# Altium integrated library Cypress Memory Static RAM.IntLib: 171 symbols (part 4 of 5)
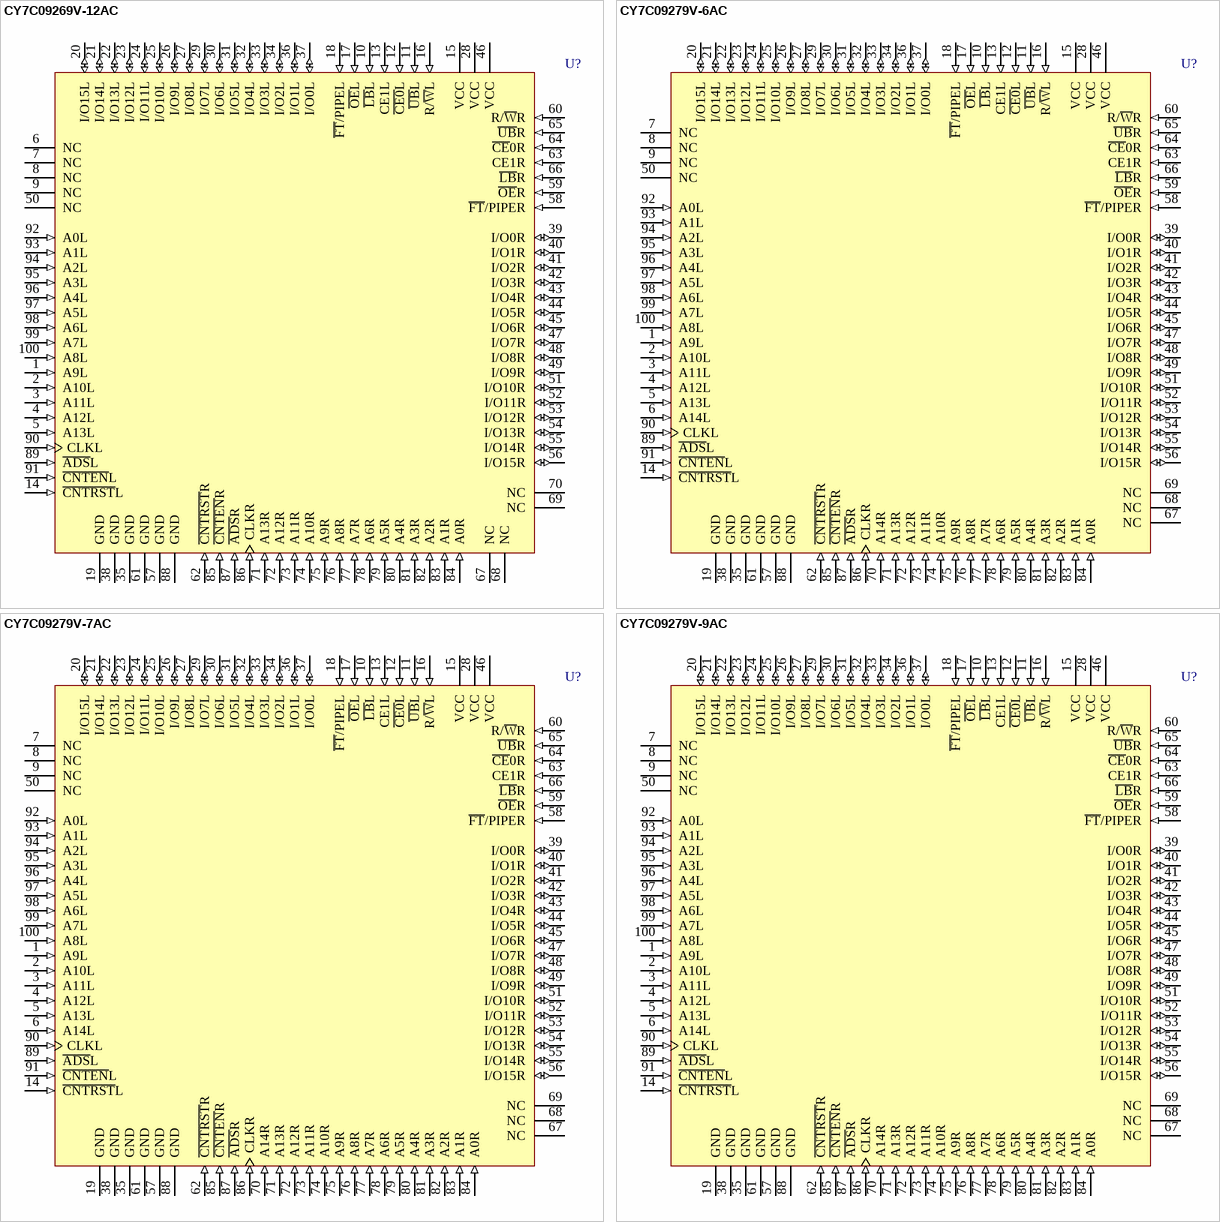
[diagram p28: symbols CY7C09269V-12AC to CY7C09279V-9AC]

## CY7C09279V-7AC
designator U?
3.3V 32K x 16 Synchronous Dual-Port Static RAM
footprint A100_N (Thin QFP, 100-Leads, Body 14x14mm, Pitch 0.5mm, IPC Medium Density)
footprint A100_L (Thin QFP, 100-Leads, Body 14x14mm, Pitch 0.5mm, IPC High Density)
footprint A100_M (Thin QFP, 100-Leads, Body 14x14mm, Pitch 0.5mm, IPC Low Density)
3D model CY7C09279V-A100 (100-Pin Thin Quad Flat Pack 0.5 mm Pitch)
pins: 1 A9L (in), 2 A10L (in), 3 A11L (in), 4 A12L (in), 5 A13L (in), 6 A14L (in), 7 NC, 8 NC, 9 NC, 10 ~{LB}L (in), 11 ~{UB}L (in), 12 ~{CE0}L (in), 13 CE1L (in), 14 ~{CNTRST}L (in), 15 VCC (power), 16 R/~{W}L (in), 17 ~{OE}L (in), 18 ~{FT}/PIPEL (in), 19 GND (power), 20 I/O15L (io), 21 I/O14L (io), 22 I/O13L (io), 23 I/O12L (io), 24 I/O11L (io), 25 I/O10L (io), 26 I/O9L (io), 27 I/O8L (io), 28 VCC (power), 29 I/O7L (io), 30 I/O6L (io), 31 I/O5L (io), 32 I/O4L (io), 33 I/O3L (io), 34 I/O2L (io), 35 GND (power), 36 I/O1L (io), 37 I/O0L (io), 38 GND (power), 39 I/O0R (io), 40 I/O1R (io), 41 I/O2R (io), 42 I/O3R (io), 43 I/O4R (io), 44 I/O5R (io), 45 I/O6R (io), 46 VCC (power), 47 I/O7R (io), 48 I/O8R (io), 49 I/O9R (io), 50 NC, 51 I/O10R (io), 52 I/O11R (io), 53 I/O12R (io), 54 I/O13R (io), 55 I/O14R (io), 56 I/O15R (io), 57 GND (power), 58 ~{FT}/PIPER (in), 59 ~{OE}R (in), 60 R/~{W}R (in), 61 GND (power), 62 ~{CNTRST}R (in), 63 CE1R (in), 64 ~{CE}0R (in), 65 ~{UB}R (in), 66 ~{LB}R (in), 67 NC, 68 NC, 69 NC, 70 A14R (in), 71 A13R (in), 72 A12R (in), 73 A11R (in), 74 A10R (in), 75 A9R (in), 76 A8R (in), 77 A7R (in), 78 A6R (in), 79 A5R (in), 80 A4R (in), 81 A3R (in), 82 A2R (in), 83 A1R (in), 84 A0R (in), 85 ~{CNTEN}R (in), 86 CLKR (in), 87 ~{ADS}R (in), 88 GND (power), 89 ~{ADS}L (in), 90 CLKL (in), 91 ~{CNTEN}L (in), 92 A0L (in), 93 A1L (in), 94 A2L (in), 95 A3L (in), 96 A4L (in), 97 A5L (in), 98 A6L (in), 99 A7L (in), 100 A8L (in)

## CY7C09279V-9AC
designator U?
3.3V 32K x 16 Synchronous Dual-Port Static RAM
footprint A100_N (Thin QFP, 100-Leads, Body 14x14mm, Pitch 0.5mm, IPC Medium Density)
footprint A100_L (Thin QFP, 100-Leads, Body 14x14mm, Pitch 0.5mm, IPC High Density)
footprint A100_M (Thin QFP, 100-Leads, Body 14x14mm, Pitch 0.5mm, IPC Low Density)
3D model CY7C09279V-A100 (100-Pin Thin Quad Flat Pack 0.5 mm Pitch)
pins: 1 A9L (in), 2 A10L (in), 3 A11L (in), 4 A12L (in), 5 A13L (in), 6 A14L (in), 7 NC, 8 NC, 9 NC, 10 ~{LB}L (in), 11 ~{UB}L (in), 12 ~{CE0}L (in), 13 CE1L (in), 14 ~{CNTRST}L (in), 15 VCC (power), 16 R/~{W}L (in), 17 ~{OE}L (in), 18 ~{FT}/PIPEL (in), 19 GND (power), 20 I/O15L (io), 21 I/O14L (io), 22 I/O13L (io), 23 I/O12L (io), 24 I/O11L (io), 25 I/O10L (io), 26 I/O9L (io), 27 I/O8L (io), 28 VCC (power), 29 I/O7L (io), 30 I/O6L (io), 31 I/O5L (io), 32 I/O4L (io), 33 I/O3L (io), 34 I/O2L (io), 35 GND (power), 36 I/O1L (io), 37 I/O0L (io), 38 GND (power), 39 I/O0R (io), 40 I/O1R (io), 41 I/O2R (io), 42 I/O3R (io), 43 I/O4R (io), 44 I/O5R (io), 45 I/O6R (io), 46 VCC (power), 47 I/O7R (io), 48 I/O8R (io), 49 I/O9R (io), 50 NC, 51 I/O10R (io), 52 I/O11R (io), 53 I/O12R (io), 54 I/O13R (io), 55 I/O14R (io), 56 I/O15R (io), 57 GND (power), 58 ~{FT}/PIPER (in), 59 ~{OE}R (in), 60 R/~{W}R (in), 61 GND (power), 62 ~{CNTRST}R (in), 63 CE1R (in), 64 ~{CE}0R (in), 65 ~{UB}R (in), 66 ~{LB}R (in), 67 NC, 68 NC, 69 NC, 70 A14R (in), 71 A13R (in), 72 A12R (in), 73 A11R (in), 74 A10R (in), 75 A9R (in), 76 A8R (in), 77 A7R (in), 78 A6R (in), 79 A5R (in), 80 A4R (in), 81 A3R (in), 82 A2R (in), 83 A1R (in), 84 A0R (in), 85 ~{CNTEN}R (in), 86 CLKR (in), 87 ~{ADS}R (in), 88 GND (power), 89 ~{ADS}L (in), 90 CLKL (in), 91 ~{CNTEN}L (in), 92 A0L (in), 93 A1L (in), 94 A2L (in), 95 A3L (in), 96 A4L (in), 97 A5L (in), 98 A6L (in), 99 A7L (in), 100 A8L (in)

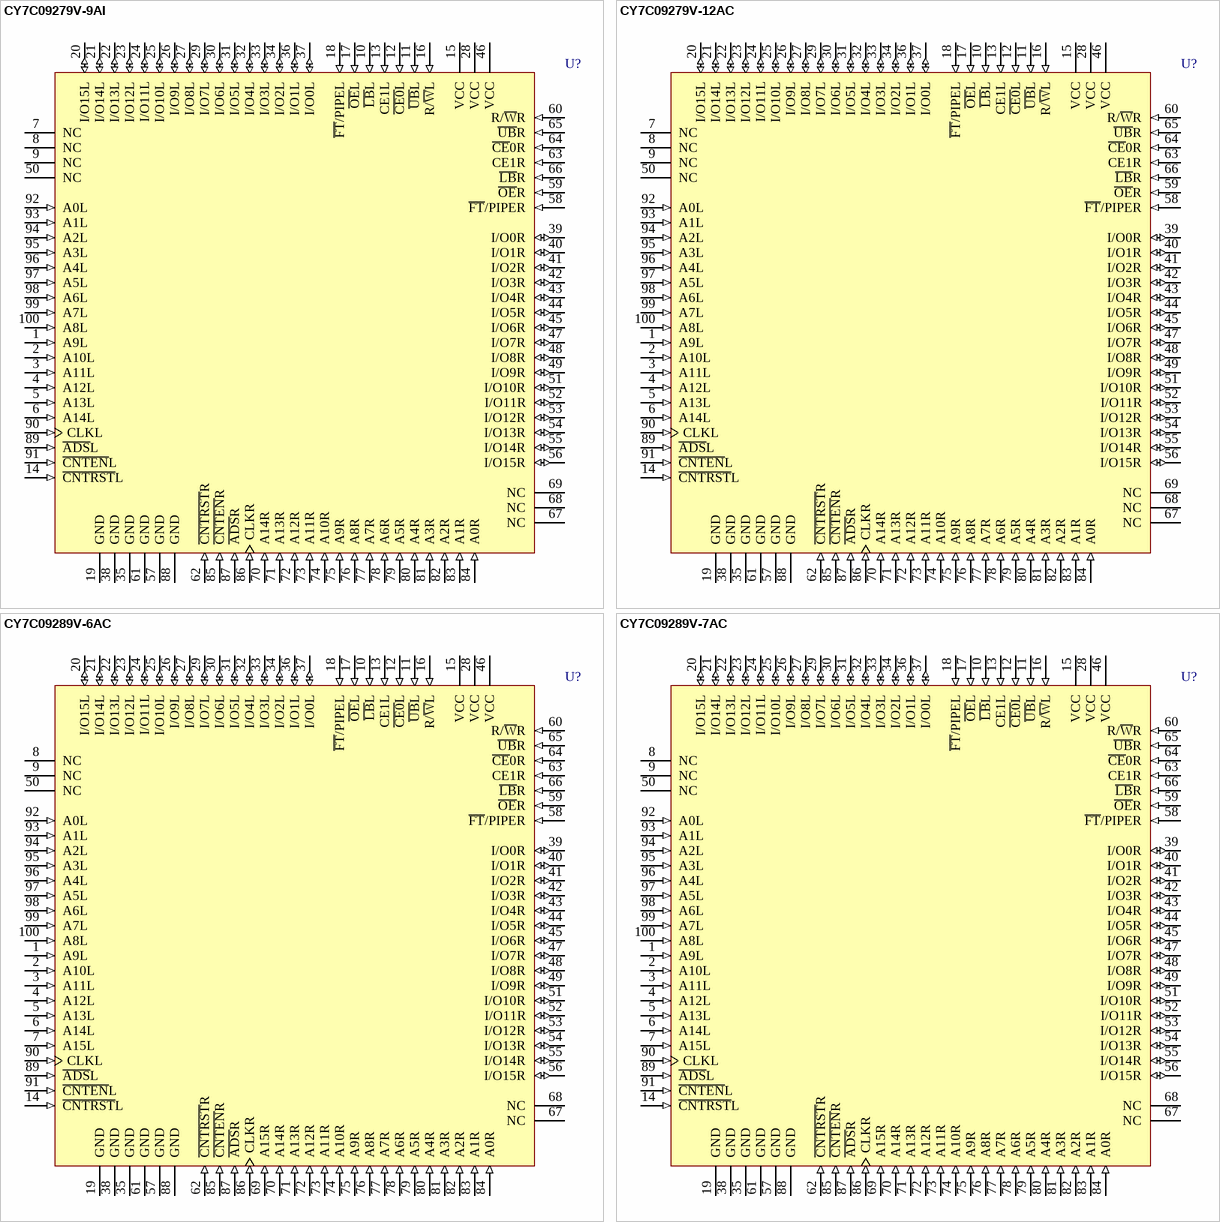
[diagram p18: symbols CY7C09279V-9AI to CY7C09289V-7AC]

## CY7C09279V-9AI
designator U?
3.3V 32K x 16 Synchronous Dual-Port Static RAM
footprint A100_N (Thin QFP, 100-Leads, Body 14x14mm, Pitch 0.5mm, IPC Medium Density)
footprint A100_L (Thin QFP, 100-Leads, Body 14x14mm, Pitch 0.5mm, IPC High Density)
footprint A100_M (Thin QFP, 100-Leads, Body 14x14mm, Pitch 0.5mm, IPC Low Density)
3D model CY7C09279V-A100 (100-Pin Thin Quad Flat Pack 0.5 mm Pitch)
pins: 1 A9L (in), 2 A10L (in), 3 A11L (in), 4 A12L (in), 5 A13L (in), 6 A14L (in), 7 NC, 8 NC, 9 NC, 10 ~{LB}L (in), 11 ~{UB}L (in), 12 ~{CE0}L (in), 13 CE1L (in), 14 ~{CNTRST}L (in), 15 VCC (power), 16 R/~{W}L (in), 17 ~{OE}L (in), 18 ~{FT}/PIPEL (in), 19 GND (power), 20 I/O15L (io), 21 I/O14L (io), 22 I/O13L (io), 23 I/O12L (io), 24 I/O11L (io), 25 I/O10L (io), 26 I/O9L (io), 27 I/O8L (io), 28 VCC (power), 29 I/O7L (io), 30 I/O6L (io), 31 I/O5L (io), 32 I/O4L (io), 33 I/O3L (io), 34 I/O2L (io), 35 GND (power), 36 I/O1L (io), 37 I/O0L (io), 38 GND (power), 39 I/O0R (io), 40 I/O1R (io), 41 I/O2R (io), 42 I/O3R (io), 43 I/O4R (io), 44 I/O5R (io), 45 I/O6R (io), 46 VCC (power), 47 I/O7R (io), 48 I/O8R (io), 49 I/O9R (io), 50 NC, 51 I/O10R (io), 52 I/O11R (io), 53 I/O12R (io), 54 I/O13R (io), 55 I/O14R (io), 56 I/O15R (io), 57 GND (power), 58 ~{FT}/PIPER (in), 59 ~{OE}R (in), 60 R/~{W}R (in), 61 GND (power), 62 ~{CNTRST}R (in), 63 CE1R (in), 64 ~{CE}0R (in), 65 ~{UB}R (in), 66 ~{LB}R (in), 67 NC, 68 NC, 69 NC, 70 A14R (in), 71 A13R (in), 72 A12R (in), 73 A11R (in), 74 A10R (in), 75 A9R (in), 76 A8R (in), 77 A7R (in), 78 A6R (in), 79 A5R (in), 80 A4R (in), 81 A3R (in), 82 A2R (in), 83 A1R (in), 84 A0R (in), 85 ~{CNTEN}R (in), 86 CLKR (in), 87 ~{ADS}R (in), 88 GND (power), 89 ~{ADS}L (in), 90 CLKL (in), 91 ~{CNTEN}L (in), 92 A0L (in), 93 A1L (in), 94 A2L (in), 95 A3L (in), 96 A4L (in), 97 A5L (in), 98 A6L (in), 99 A7L (in), 100 A8L (in)

## CY7C09279V-12AC
designator U?
3.3V 32K x 16 Synchronous Dual-Port Static RAM
footprint A100_N (Thin QFP, 100-Leads, Body 14x14mm, Pitch 0.5mm, IPC Medium Density)
footprint A100_L (Thin QFP, 100-Leads, Body 14x14mm, Pitch 0.5mm, IPC High Density)
footprint A100_M (Thin QFP, 100-Leads, Body 14x14mm, Pitch 0.5mm, IPC Low Density)
3D model CY7C09279V-A100 (100-Pin Thin Quad Flat Pack 0.5 mm Pitch)
pins: 1 A9L (in), 2 A10L (in), 3 A11L (in), 4 A12L (in), 5 A13L (in), 6 A14L (in), 7 NC, 8 NC, 9 NC, 10 ~{LB}L (in), 11 ~{UB}L (in), 12 ~{CE0}L (in), 13 CE1L (in), 14 ~{CNTRST}L (in), 15 VCC (power), 16 R/~{W}L (in), 17 ~{OE}L (in), 18 ~{FT}/PIPEL (in), 19 GND (power), 20 I/O15L (io), 21 I/O14L (io), 22 I/O13L (io), 23 I/O12L (io), 24 I/O11L (io), 25 I/O10L (io), 26 I/O9L (io), 27 I/O8L (io), 28 VCC (power), 29 I/O7L (io), 30 I/O6L (io), 31 I/O5L (io), 32 I/O4L (io), 33 I/O3L (io), 34 I/O2L (io), 35 GND (power), 36 I/O1L (io), 37 I/O0L (io), 38 GND (power), 39 I/O0R (io), 40 I/O1R (io), 41 I/O2R (io), 42 I/O3R (io), 43 I/O4R (io), 44 I/O5R (io), 45 I/O6R (io), 46 VCC (power), 47 I/O7R (io), 48 I/O8R (io), 49 I/O9R (io), 50 NC, 51 I/O10R (io), 52 I/O11R (io), 53 I/O12R (io), 54 I/O13R (io), 55 I/O14R (io), 56 I/O15R (io), 57 GND (power), 58 ~{FT}/PIPER (in), 59 ~{OE}R (in), 60 R/~{W}R (in), 61 GND (power), 62 ~{CNTRST}R (in), 63 CE1R (in), 64 ~{CE}0R (in), 65 ~{UB}R (in), 66 ~{LB}R (in), 67 NC, 68 NC, 69 NC, 70 A14R (in), 71 A13R (in), 72 A12R (in), 73 A11R (in), 74 A10R (in), 75 A9R (in), 76 A8R (in), 77 A7R (in), 78 A6R (in), 79 A5R (in), 80 A4R (in), 81 A3R (in), 82 A2R (in), 83 A1R (in), 84 A0R (in), 85 ~{CNTEN}R (in), 86 CLKR (in), 87 ~{ADS}R (in), 88 GND (power), 89 ~{ADS}L (in), 90 CLKL (in), 91 ~{CNTEN}L (in), 92 A0L (in), 93 A1L (in), 94 A2L (in), 95 A3L (in), 96 A4L (in), 97 A5L (in), 98 A6L (in), 99 A7L (in), 100 A8L (in)

## CY7C09289V-6AC
designator U?
3.3V 64K x 16 Synchronous Dual-Port Static RAM
footprint A100_N (Thin QFP, 100-Leads, Body 14x14mm, Pitch 0.5mm, IPC Medium Density)
footprint A100_L (Thin QFP, 100-Leads, Body 14x14mm, Pitch 0.5mm, IPC High Density)
footprint A100_M (Thin QFP, 100-Leads, Body 14x14mm, Pitch 0.5mm, IPC Low Density)
3D model CY7C09289V-A100 (100-Pin Thin Quad Flat Pack 0.5 mm Pitch)
pins: 1 A9L (in), 2 A10L (in), 3 A11L (in), 4 A12L (in), 5 A13L (in), 6 A14L (in), 7 A15L (in), 8 NC, 9 NC, 10 ~{LB}L (in), 11 ~{UB}L (in), 12 ~{CE0}L (in), 13 CE1L (in), 14 ~{CNTRST}L (in), 15 VCC (power), 16 R/~{W}L (in), 17 ~{OE}L (in), 18 ~{FT}/PIPEL (in), 19 GND (power), 20 I/O15L (io), 21 I/O14L (io), 22 I/O13L (io), 23 I/O12L (io), 24 I/O11L (io), 25 I/O10L (io), 26 I/O9L (io), 27 I/O8L (io), 28 VCC (power), 29 I/O7L (io), 30 I/O6L (io), 31 I/O5L (io), 32 I/O4L (io), 33 I/O3L (io), 34 I/O2L (io), 35 GND (power), 36 I/O1L (io), 37 I/O0L (io), 38 GND (power), 39 I/O0R (io), 40 I/O1R (io), 41 I/O2R (io), 42 I/O3R (io), 43 I/O4R (io), 44 I/O5R (io), 45 I/O6R (io), 46 VCC (power), 47 I/O7R (io), 48 I/O8R (io), 49 I/O9R (io), 50 NC, 51 I/O10R (io), 52 I/O11R (io), 53 I/O12R (io), 54 I/O13R (io), 55 I/O14R (io), 56 I/O15R (io), 57 GND (power), 58 ~{FT}/PIPER (in), 59 ~{OE}R (in), 60 R/~{W}R (in), 61 GND (power), 62 ~{CNTRST}R (in), 63 CE1R (in), 64 ~{CE}0R (in), 65 ~{UB}R (in), 66 ~{LB}R (in), 67 NC, 68 NC, 69 A15R (in), 70 A14R (in), 71 A13R (in), 72 A12R (in), 73 A11R (in), 74 A10R (in), 75 A9R (in), 76 A8R (in), 77 A7R (in), 78 A6R (in), 79 A5R (in), 80 A4R (in), 81 A3R (in), 82 A2R (in), 83 A1R (in), 84 A0R (in), 85 ~{CNTEN}R (in), 86 CLKR (in), 87 ~{ADS}R (in), 88 GND (power), 89 ~{ADS}L (in), 90 CLKL (in), 91 ~{CNTEN}L (in), 92 A0L (in), 93 A1L (in), 94 A2L (in), 95 A3L (in), 96 A4L (in), 97 A5L (in), 98 A6L (in), 99 A7L (in), 100 A8L (in)

## CY7C09289V-7AC
designator U?
3.3V 64K x 16 Synchronous Dual-Port Static RAM
footprint A100_N (Thin QFP, 100-Leads, Body 14x14mm, Pitch 0.5mm, IPC Medium Density)
footprint A100_L (Thin QFP, 100-Leads, Body 14x14mm, Pitch 0.5mm, IPC High Density)
footprint A100_M (Thin QFP, 100-Leads, Body 14x14mm, Pitch 0.5mm, IPC Low Density)
3D model CY7C09289V-A100 (100-Pin Thin Quad Flat Pack 0.5 mm Pitch)
pins: 1 A9L (in), 2 A10L (in), 3 A11L (in), 4 A12L (in), 5 A13L (in), 6 A14L (in), 7 A15L (in), 8 NC, 9 NC, 10 ~{LB}L (in), 11 ~{UB}L (in), 12 ~{CE0}L (in), 13 CE1L (in), 14 ~{CNTRST}L (in), 15 VCC (power), 16 R/~{W}L (in), 17 ~{OE}L (in), 18 ~{FT}/PIPEL (in), 19 GND (power), 20 I/O15L (io), 21 I/O14L (io), 22 I/O13L (io), 23 I/O12L (io), 24 I/O11L (io), 25 I/O10L (io), 26 I/O9L (io), 27 I/O8L (io), 28 VCC (power), 29 I/O7L (io), 30 I/O6L (io), 31 I/O5L (io), 32 I/O4L (io), 33 I/O3L (io), 34 I/O2L (io), 35 GND (power), 36 I/O1L (io), 37 I/O0L (io), 38 GND (power), 39 I/O0R (io), 40 I/O1R (io), 41 I/O2R (io), 42 I/O3R (io), 43 I/O4R (io), 44 I/O5R (io), 45 I/O6R (io), 46 VCC (power), 47 I/O7R (io), 48 I/O8R (io), 49 I/O9R (io), 50 NC, 51 I/O10R (io), 52 I/O11R (io), 53 I/O12R (io), 54 I/O13R (io), 55 I/O14R (io), 56 I/O15R (io), 57 GND (power), 58 ~{FT}/PIPER (in), 59 ~{OE}R (in), 60 R/~{W}R (in), 61 GND (power), 62 ~{CNTRST}R (in), 63 CE1R (in), 64 ~{CE}0R (in), 65 ~{UB}R (in), 66 ~{LB}R (in), 67 NC, 68 NC, 69 A15R (in), 70 A14R (in), 71 A13R (in), 72 A12R (in), 73 A11R (in), 74 A10R (in), 75 A9R (in), 76 A8R (in), 77 A7R (in), 78 A6R (in), 79 A5R (in), 80 A4R (in), 81 A3R (in), 82 A2R (in), 83 A1R (in), 84 A0R (in), 85 ~{CNTEN}R (in), 86 CLKR (in), 87 ~{ADS}R (in), 88 GND (power), 89 ~{ADS}L (in), 90 CLKL (in), 91 ~{CNTEN}L (in), 92 A0L (in), 93 A1L (in), 94 A2L (in), 95 A3L (in), 96 A4L (in), 97 A5L (in), 98 A6L (in), 99 A7L (in), 100 A8L (in)

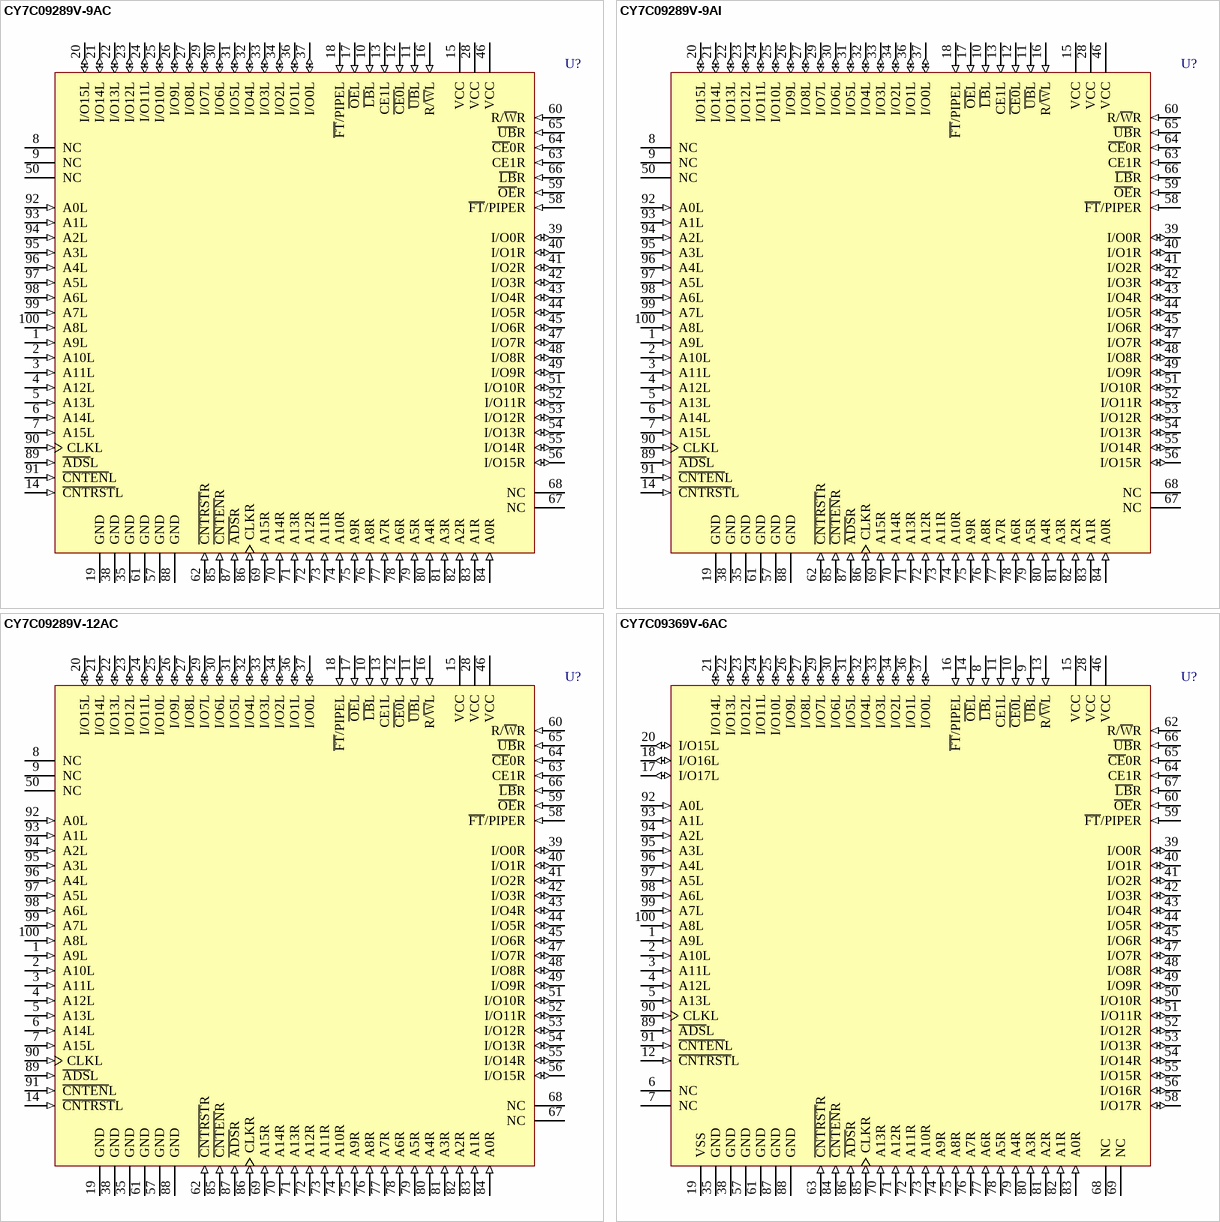
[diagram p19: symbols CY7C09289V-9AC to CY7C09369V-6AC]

## CY7C09289V-9AC
designator U?
3.3V 64K x 16 Synchronous Dual-Port Static RAM
footprint A100_N (Thin QFP, 100-Leads, Body 14x14mm, Pitch 0.5mm, IPC Medium Density)
footprint A100_L (Thin QFP, 100-Leads, Body 14x14mm, Pitch 0.5mm, IPC High Density)
footprint A100_M (Thin QFP, 100-Leads, Body 14x14mm, Pitch 0.5mm, IPC Low Density)
3D model CY7C09289V-A100 (100-Pin Thin Quad Flat Pack 0.5 mm Pitch)
pins: 1 A9L (in), 2 A10L (in), 3 A11L (in), 4 A12L (in), 5 A13L (in), 6 A14L (in), 7 A15L (in), 8 NC, 9 NC, 10 ~{LB}L (in), 11 ~{UB}L (in), 12 ~{CE0}L (in), 13 CE1L (in), 14 ~{CNTRST}L (in), 15 VCC (power), 16 R/~{W}L (in), 17 ~{OE}L (in), 18 ~{FT}/PIPEL (in), 19 GND (power), 20 I/O15L (io), 21 I/O14L (io), 22 I/O13L (io), 23 I/O12L (io), 24 I/O11L (io), 25 I/O10L (io), 26 I/O9L (io), 27 I/O8L (io), 28 VCC (power), 29 I/O7L (io), 30 I/O6L (io), 31 I/O5L (io), 32 I/O4L (io), 33 I/O3L (io), 34 I/O2L (io), 35 GND (power), 36 I/O1L (io), 37 I/O0L (io), 38 GND (power), 39 I/O0R (io), 40 I/O1R (io), 41 I/O2R (io), 42 I/O3R (io), 43 I/O4R (io), 44 I/O5R (io), 45 I/O6R (io), 46 VCC (power), 47 I/O7R (io), 48 I/O8R (io), 49 I/O9R (io), 50 NC, 51 I/O10R (io), 52 I/O11R (io), 53 I/O12R (io), 54 I/O13R (io), 55 I/O14R (io), 56 I/O15R (io), 57 GND (power), 58 ~{FT}/PIPER (in), 59 ~{OE}R (in), 60 R/~{W}R (in), 61 GND (power), 62 ~{CNTRST}R (in), 63 CE1R (in), 64 ~{CE}0R (in), 65 ~{UB}R (in), 66 ~{LB}R (in), 67 NC, 68 NC, 69 A15R (in), 70 A14R (in), 71 A13R (in), 72 A12R (in), 73 A11R (in), 74 A10R (in), 75 A9R (in), 76 A8R (in), 77 A7R (in), 78 A6R (in), 79 A5R (in), 80 A4R (in), 81 A3R (in), 82 A2R (in), 83 A1R (in), 84 A0R (in), 85 ~{CNTEN}R (in), 86 CLKR (in), 87 ~{ADS}R (in), 88 GND (power), 89 ~{ADS}L (in), 90 CLKL (in), 91 ~{CNTEN}L (in), 92 A0L (in), 93 A1L (in), 94 A2L (in), 95 A3L (in), 96 A4L (in), 97 A5L (in), 98 A6L (in), 99 A7L (in), 100 A8L (in)

## CY7C09289V-9AI
designator U?
3.3V 64K x 16 Synchronous Dual-Port Static RAM
footprint A100_N (Thin QFP, 100-Leads, Body 14x14mm, Pitch 0.5mm, IPC Medium Density)
footprint A100_L (Thin QFP, 100-Leads, Body 14x14mm, Pitch 0.5mm, IPC High Density)
footprint A100_M (Thin QFP, 100-Leads, Body 14x14mm, Pitch 0.5mm, IPC Low Density)
3D model CY7C09289V-A100 (100-Pin Thin Quad Flat Pack 0.5 mm Pitch)
pins: 1 A9L (in), 2 A10L (in), 3 A11L (in), 4 A12L (in), 5 A13L (in), 6 A14L (in), 7 A15L (in), 8 NC, 9 NC, 10 ~{LB}L (in), 11 ~{UB}L (in), 12 ~{CE0}L (in), 13 CE1L (in), 14 ~{CNTRST}L (in), 15 VCC (power), 16 R/~{W}L (in), 17 ~{OE}L (in), 18 ~{FT}/PIPEL (in), 19 GND (power), 20 I/O15L (io), 21 I/O14L (io), 22 I/O13L (io), 23 I/O12L (io), 24 I/O11L (io), 25 I/O10L (io), 26 I/O9L (io), 27 I/O8L (io), 28 VCC (power), 29 I/O7L (io), 30 I/O6L (io), 31 I/O5L (io), 32 I/O4L (io), 33 I/O3L (io), 34 I/O2L (io), 35 GND (power), 36 I/O1L (io), 37 I/O0L (io), 38 GND (power), 39 I/O0R (io), 40 I/O1R (io), 41 I/O2R (io), 42 I/O3R (io), 43 I/O4R (io), 44 I/O5R (io), 45 I/O6R (io), 46 VCC (power), 47 I/O7R (io), 48 I/O8R (io), 49 I/O9R (io), 50 NC, 51 I/O10R (io), 52 I/O11R (io), 53 I/O12R (io), 54 I/O13R (io), 55 I/O14R (io), 56 I/O15R (io), 57 GND (power), 58 ~{FT}/PIPER (in), 59 ~{OE}R (in), 60 R/~{W}R (in), 61 GND (power), 62 ~{CNTRST}R (in), 63 CE1R (in), 64 ~{CE}0R (in), 65 ~{UB}R (in), 66 ~{LB}R (in), 67 NC, 68 NC, 69 A15R (in), 70 A14R (in), 71 A13R (in), 72 A12R (in), 73 A11R (in), 74 A10R (in), 75 A9R (in), 76 A8R (in), 77 A7R (in), 78 A6R (in), 79 A5R (in), 80 A4R (in), 81 A3R (in), 82 A2R (in), 83 A1R (in), 84 A0R (in), 85 ~{CNTEN}R (in), 86 CLKR (in), 87 ~{ADS}R (in), 88 GND (power), 89 ~{ADS}L (in), 90 CLKL (in), 91 ~{CNTEN}L (in), 92 A0L (in), 93 A1L (in), 94 A2L (in), 95 A3L (in), 96 A4L (in), 97 A5L (in), 98 A6L (in), 99 A7L (in), 100 A8L (in)

## CY7C09289V-12AC
designator U?
3.3V 64K x 16 Synchronous Dual-Port Static RAM
footprint A100_N (Thin QFP, 100-Leads, Body 14x14mm, Pitch 0.5mm, IPC Medium Density)
footprint A100_L (Thin QFP, 100-Leads, Body 14x14mm, Pitch 0.5mm, IPC High Density)
footprint A100_M (Thin QFP, 100-Leads, Body 14x14mm, Pitch 0.5mm, IPC Low Density)
3D model CY7C09289V-A100 (100-Pin Thin Quad Flat Pack 0.5 mm Pitch)
pins: 1 A9L (in), 2 A10L (in), 3 A11L (in), 4 A12L (in), 5 A13L (in), 6 A14L (in), 7 A15L (in), 8 NC, 9 NC, 10 ~{LB}L (in), 11 ~{UB}L (in), 12 ~{CE0}L (in), 13 CE1L (in), 14 ~{CNTRST}L (in), 15 VCC (power), 16 R/~{W}L (in), 17 ~{OE}L (in), 18 ~{FT}/PIPEL (in), 19 GND (power), 20 I/O15L (io), 21 I/O14L (io), 22 I/O13L (io), 23 I/O12L (io), 24 I/O11L (io), 25 I/O10L (io), 26 I/O9L (io), 27 I/O8L (io), 28 VCC (power), 29 I/O7L (io), 30 I/O6L (io), 31 I/O5L (io), 32 I/O4L (io), 33 I/O3L (io), 34 I/O2L (io), 35 GND (power), 36 I/O1L (io), 37 I/O0L (io), 38 GND (power), 39 I/O0R (io), 40 I/O1R (io), 41 I/O2R (io), 42 I/O3R (io), 43 I/O4R (io), 44 I/O5R (io), 45 I/O6R (io), 46 VCC (power), 47 I/O7R (io), 48 I/O8R (io), 49 I/O9R (io), 50 NC, 51 I/O10R (io), 52 I/O11R (io), 53 I/O12R (io), 54 I/O13R (io), 55 I/O14R (io), 56 I/O15R (io), 57 GND (power), 58 ~{FT}/PIPER (in), 59 ~{OE}R (in), 60 R/~{W}R (in), 61 GND (power), 62 ~{CNTRST}R (in), 63 CE1R (in), 64 ~{CE}0R (in), 65 ~{UB}R (in), 66 ~{LB}R (in), 67 NC, 68 NC, 69 A15R (in), 70 A14R (in), 71 A13R (in), 72 A12R (in), 73 A11R (in), 74 A10R (in), 75 A9R (in), 76 A8R (in), 77 A7R (in), 78 A6R (in), 79 A5R (in), 80 A4R (in), 81 A3R (in), 82 A2R (in), 83 A1R (in), 84 A0R (in), 85 ~{CNTEN}R (in), 86 CLKR (in), 87 ~{ADS}R (in), 88 GND (power), 89 ~{ADS}L (in), 90 CLKL (in), 91 ~{CNTEN}L (in), 92 A0L (in), 93 A1L (in), 94 A2L (in), 95 A3L (in), 96 A4L (in), 97 A5L (in), 98 A6L (in), 99 A7L (in), 100 A8L (in)

## CY7C09369V-6AC
designator U?
3.3V 16K x 18 Synchronous Dual-Port Static RAM
footprint A100_N (Thin QFP, 100-Leads, Body 14x14mm, Pitch 0.5mm, IPC Medium Density)
footprint A100_L (Thin QFP, 100-Leads, Body 14x14mm, Pitch 0.5mm, IPC High Density)
footprint A100_M (Thin QFP, 100-Leads, Body 14x14mm, Pitch 0.5mm, IPC Low Density)
3D model CY7C09369V-A100 (100-Pin Thin Quad Flat Pack 0.5 mm Pitch)
pins: 1 A9L (in), 2 A10L (in), 3 A11L (in), 4 A12L (in), 5 A13L (in), 6 NC, 7 NC, 8 ~{LB}L (in), 9 ~{UB}L (in), 10 ~{CE0}L (in), 11 CE1L (in), 12 ~{CNTRST}L (in), 13 R/~{W}L (in), 14 ~{OE}L (in), 15 VCC (power), 16 ~{FT}/PIPEL (in), 17 I/O17L (io), 18 I/O16L (io), 19 VSS (power), 20 I/O15L (io), 21 I/O14L (io), 22 I/O13L (io), 23 I/O12L (io), 24 I/O11L (io), 25 I/O10L (io), 26 I/O9L (io), 27 I/O8L (io), 28 VCC (power), 29 I/O7L (io), 30 I/O6L (io), 31 I/O5L (io), 32 I/O4L (io), 33 I/O3L (io), 34 I/O2L (io), 35 GND (power), 36 I/O1L (io), 37 I/O0L (io), 38 GND (power), 39 I/O0R (io), 40 I/O1R (io), 41 I/O2R (io), 42 I/O3R (io), 43 I/O4R (io), 44 I/O5R (io), 45 I/O6R (io), 46 VCC (power), 47 I/O7R (io), 48 I/O8R (io), 49 I/O9R (io), 50 I/O10R (io), 51 I/O11R (io), 52 I/O12R (io), 53 I/O13R (io), 54 I/O14R (io), 55 I/O15R (io), 56 I/O16R (io), 57 GND (power), 58 I/O17R (io), 59 ~{FT}/PIPER (in), 60 ~{OE}R (in), 61 GND (power), 62 R/~{W}R (in), 63 ~{CNTRST}R (in), 64 CE1R (in), 65 ~{CE}0R (in), 66 ~{UB}R (in), 67 ~{LB}R (in), 68 NC, 69 NC, 70 A13R (in), 71 A12R (in), 72 A11R (in), 73 A10R (in), 74 A9R (in), 75 A8R (in), 76 A7R (in), 77 A6R (in), 78 A5R (in), 79 A4R (in), 80 A3R (in), 81 A2R (in), 82 A1R (in), 83 A0R (in), 84 ~{CNTEN}R (in), 85 CLKR (in), 86 ~{ADS}R (in), 87 GND (power), 88 GND (power), 89 ~{ADS}L (in), 90 CLKL (in), 91 ~{CNTEN}L (in), 92 A0L (in), 93 A1L (in), 94 A2L (in), 95 A3L (in), 96 A4L (in), 97 A5L (in), 98 A6L (in), 99 A7L (in), 100 A8L (in)

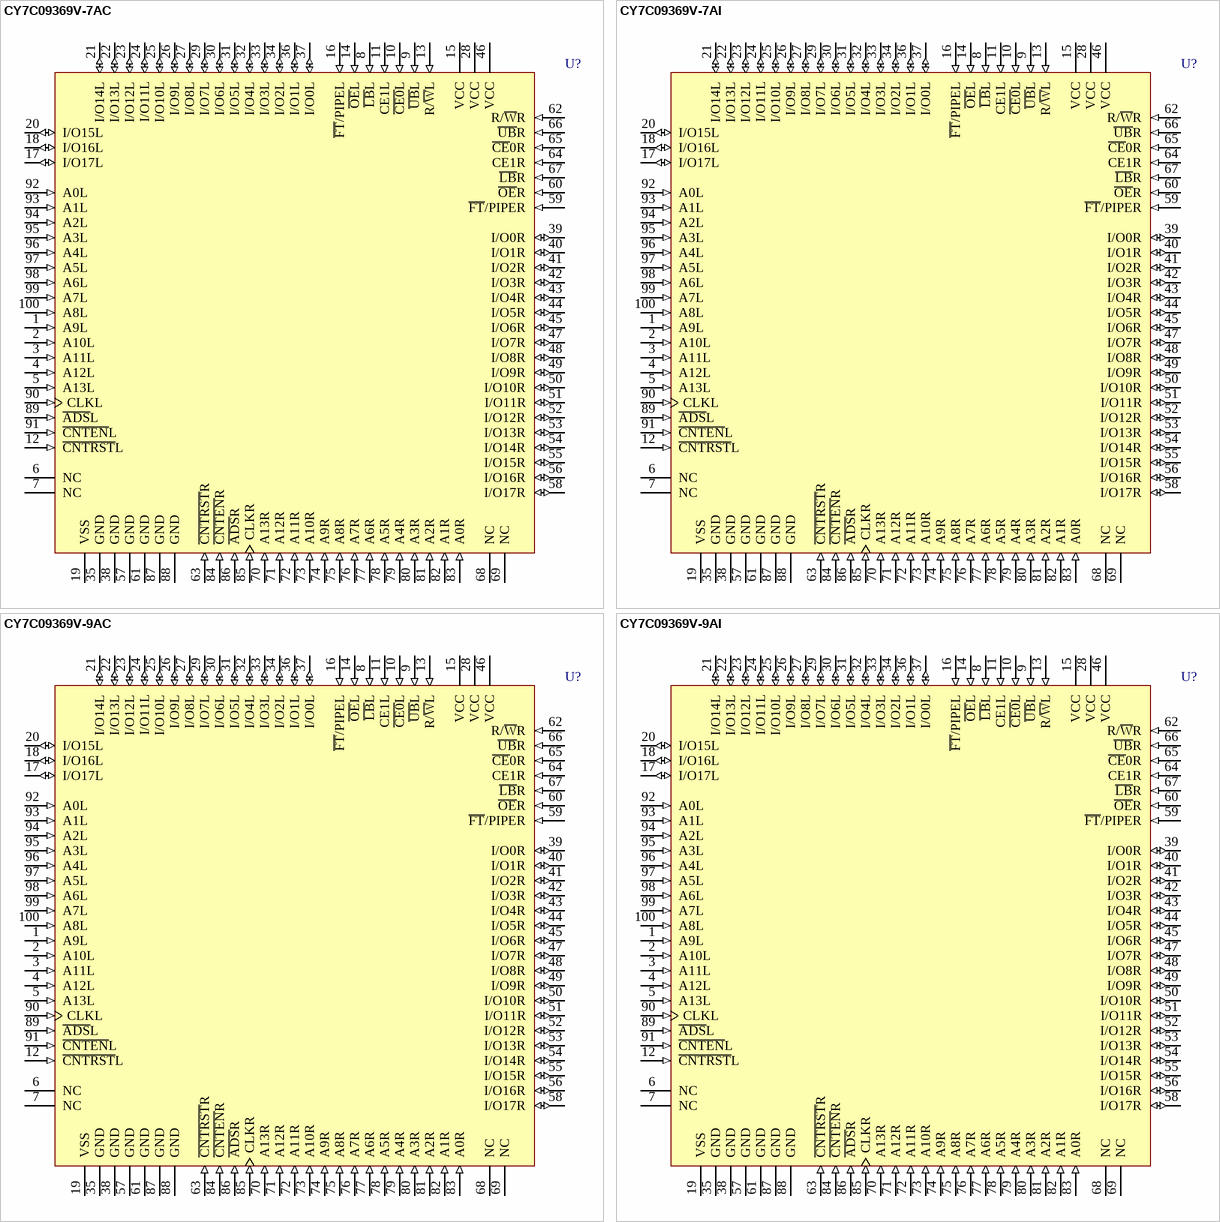
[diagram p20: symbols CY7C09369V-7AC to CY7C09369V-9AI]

## CY7C09369V-7AC
designator U?
3.3V 16K x 18 Synchronous Dual-Port Static RAM
footprint A100_N (Thin QFP, 100-Leads, Body 14x14mm, Pitch 0.5mm, IPC Medium Density)
footprint A100_L (Thin QFP, 100-Leads, Body 14x14mm, Pitch 0.5mm, IPC High Density)
footprint A100_M (Thin QFP, 100-Leads, Body 14x14mm, Pitch 0.5mm, IPC Low Density)
3D model CY7C09369V-A100 (100-Pin Thin Quad Flat Pack 0.5 mm Pitch)
pins: 1 A9L (in), 2 A10L (in), 3 A11L (in), 4 A12L (in), 5 A13L (in), 6 NC, 7 NC, 8 ~{LB}L (in), 9 ~{UB}L (in), 10 ~{CE0}L (in), 11 CE1L (in), 12 ~{CNTRST}L (in), 13 R/~{W}L (in), 14 ~{OE}L (in), 15 VCC (power), 16 ~{FT}/PIPEL (in), 17 I/O17L (io), 18 I/O16L (io), 19 VSS (power), 20 I/O15L (io), 21 I/O14L (io), 22 I/O13L (io), 23 I/O12L (io), 24 I/O11L (io), 25 I/O10L (io), 26 I/O9L (io), 27 I/O8L (io), 28 VCC (power), 29 I/O7L (io), 30 I/O6L (io), 31 I/O5L (io), 32 I/O4L (io), 33 I/O3L (io), 34 I/O2L (io), 35 GND (power), 36 I/O1L (io), 37 I/O0L (io), 38 GND (power), 39 I/O0R (io), 40 I/O1R (io), 41 I/O2R (io), 42 I/O3R (io), 43 I/O4R (io), 44 I/O5R (io), 45 I/O6R (io), 46 VCC (power), 47 I/O7R (io), 48 I/O8R (io), 49 I/O9R (io), 50 I/O10R (io), 51 I/O11R (io), 52 I/O12R (io), 53 I/O13R (io), 54 I/O14R (io), 55 I/O15R (io), 56 I/O16R (io), 57 GND (power), 58 I/O17R (io), 59 ~{FT}/PIPER (in), 60 ~{OE}R (in), 61 GND (power), 62 R/~{W}R (in), 63 ~{CNTRST}R (in), 64 CE1R (in), 65 ~{CE}0R (in), 66 ~{UB}R (in), 67 ~{LB}R (in), 68 NC, 69 NC, 70 A13R (in), 71 A12R (in), 72 A11R (in), 73 A10R (in), 74 A9R (in), 75 A8R (in), 76 A7R (in), 77 A6R (in), 78 A5R (in), 79 A4R (in), 80 A3R (in), 81 A2R (in), 82 A1R (in), 83 A0R (in), 84 ~{CNTEN}R (in), 85 CLKR (in), 86 ~{ADS}R (in), 87 GND (power), 88 GND (power), 89 ~{ADS}L (in), 90 CLKL (in), 91 ~{CNTEN}L (in), 92 A0L (in), 93 A1L (in), 94 A2L (in), 95 A3L (in), 96 A4L (in), 97 A5L (in), 98 A6L (in), 99 A7L (in), 100 A8L (in)

## CY7C09369V-7AI
designator U?
3.3V 16K x 18 Synchronous Dual-Port Static RAM
footprint A100_N (Thin QFP, 100-Leads, Body 14x14mm, Pitch 0.5mm, IPC Medium Density)
footprint A100_L (Thin QFP, 100-Leads, Body 14x14mm, Pitch 0.5mm, IPC High Density)
footprint A100_M (Thin QFP, 100-Leads, Body 14x14mm, Pitch 0.5mm, IPC Low Density)
3D model CY7C09369V-A100 (100-Pin Thin Quad Flat Pack 0.5 mm Pitch)
pins: 1 A9L (in), 2 A10L (in), 3 A11L (in), 4 A12L (in), 5 A13L (in), 6 NC, 7 NC, 8 ~{LB}L (in), 9 ~{UB}L (in), 10 ~{CE0}L (in), 11 CE1L (in), 12 ~{CNTRST}L (in), 13 R/~{W}L (in), 14 ~{OE}L (in), 15 VCC (power), 16 ~{FT}/PIPEL (in), 17 I/O17L (io), 18 I/O16L (io), 19 VSS (power), 20 I/O15L (io), 21 I/O14L (io), 22 I/O13L (io), 23 I/O12L (io), 24 I/O11L (io), 25 I/O10L (io), 26 I/O9L (io), 27 I/O8L (io), 28 VCC (power), 29 I/O7L (io), 30 I/O6L (io), 31 I/O5L (io), 32 I/O4L (io), 33 I/O3L (io), 34 I/O2L (io), 35 GND (power), 36 I/O1L (io), 37 I/O0L (io), 38 GND (power), 39 I/O0R (io), 40 I/O1R (io), 41 I/O2R (io), 42 I/O3R (io), 43 I/O4R (io), 44 I/O5R (io), 45 I/O6R (io), 46 VCC (power), 47 I/O7R (io), 48 I/O8R (io), 49 I/O9R (io), 50 I/O10R (io), 51 I/O11R (io), 52 I/O12R (io), 53 I/O13R (io), 54 I/O14R (io), 55 I/O15R (io), 56 I/O16R (io), 57 GND (power), 58 I/O17R (io), 59 ~{FT}/PIPER (in), 60 ~{OE}R (in), 61 GND (power), 62 R/~{W}R (in), 63 ~{CNTRST}R (in), 64 CE1R (in), 65 ~{CE}0R (in), 66 ~{UB}R (in), 67 ~{LB}R (in), 68 NC, 69 NC, 70 A13R (in), 71 A12R (in), 72 A11R (in), 73 A10R (in), 74 A9R (in), 75 A8R (in), 76 A7R (in), 77 A6R (in), 78 A5R (in), 79 A4R (in), 80 A3R (in), 81 A2R (in), 82 A1R (in), 83 A0R (in), 84 ~{CNTEN}R (in), 85 CLKR (in), 86 ~{ADS}R (in), 87 GND (power), 88 GND (power), 89 ~{ADS}L (in), 90 CLKL (in), 91 ~{CNTEN}L (in), 92 A0L (in), 93 A1L (in), 94 A2L (in), 95 A3L (in), 96 A4L (in), 97 A5L (in), 98 A6L (in), 99 A7L (in), 100 A8L (in)

## CY7C09369V-9AC
designator U?
3.3V 16K x 18 Synchronous Dual-Port Static RAM
footprint A100_N (Thin QFP, 100-Leads, Body 14x14mm, Pitch 0.5mm, IPC Medium Density)
footprint A100_L (Thin QFP, 100-Leads, Body 14x14mm, Pitch 0.5mm, IPC High Density)
footprint A100_M (Thin QFP, 100-Leads, Body 14x14mm, Pitch 0.5mm, IPC Low Density)
3D model CY7C09369V-A100 (100-Pin Thin Quad Flat Pack 0.5 mm Pitch)
pins: 1 A9L (in), 2 A10L (in), 3 A11L (in), 4 A12L (in), 5 A13L (in), 6 NC, 7 NC, 8 ~{LB}L (in), 9 ~{UB}L (in), 10 ~{CE0}L (in), 11 CE1L (in), 12 ~{CNTRST}L (in), 13 R/~{W}L (in), 14 ~{OE}L (in), 15 VCC (power), 16 ~{FT}/PIPEL (in), 17 I/O17L (io), 18 I/O16L (io), 19 VSS (power), 20 I/O15L (io), 21 I/O14L (io), 22 I/O13L (io), 23 I/O12L (io), 24 I/O11L (io), 25 I/O10L (io), 26 I/O9L (io), 27 I/O8L (io), 28 VCC (power), 29 I/O7L (io), 30 I/O6L (io), 31 I/O5L (io), 32 I/O4L (io), 33 I/O3L (io), 34 I/O2L (io), 35 GND (power), 36 I/O1L (io), 37 I/O0L (io), 38 GND (power), 39 I/O0R (io), 40 I/O1R (io), 41 I/O2R (io), 42 I/O3R (io), 43 I/O4R (io), 44 I/O5R (io), 45 I/O6R (io), 46 VCC (power), 47 I/O7R (io), 48 I/O8R (io), 49 I/O9R (io), 50 I/O10R (io), 51 I/O11R (io), 52 I/O12R (io), 53 I/O13R (io), 54 I/O14R (io), 55 I/O15R (io), 56 I/O16R (io), 57 GND (power), 58 I/O17R (io), 59 ~{FT}/PIPER (in), 60 ~{OE}R (in), 61 GND (power), 62 R/~{W}R (in), 63 ~{CNTRST}R (in), 64 CE1R (in), 65 ~{CE}0R (in), 66 ~{UB}R (in), 67 ~{LB}R (in), 68 NC, 69 NC, 70 A13R (in), 71 A12R (in), 72 A11R (in), 73 A10R (in), 74 A9R (in), 75 A8R (in), 76 A7R (in), 77 A6R (in), 78 A5R (in), 79 A4R (in), 80 A3R (in), 81 A2R (in), 82 A1R (in), 83 A0R (in), 84 ~{CNTEN}R (in), 85 CLKR (in), 86 ~{ADS}R (in), 87 GND (power), 88 GND (power), 89 ~{ADS}L (in), 90 CLKL (in), 91 ~{CNTEN}L (in), 92 A0L (in), 93 A1L (in), 94 A2L (in), 95 A3L (in), 96 A4L (in), 97 A5L (in), 98 A6L (in), 99 A7L (in), 100 A8L (in)

## CY7C09369V-9AI
designator U?
3.3V 16K x 18 Synchronous Dual-Port Static RAM
footprint A100_N (Thin QFP, 100-Leads, Body 14x14mm, Pitch 0.5mm, IPC Medium Density)
footprint A100_L (Thin QFP, 100-Leads, Body 14x14mm, Pitch 0.5mm, IPC High Density)
footprint A100_M (Thin QFP, 100-Leads, Body 14x14mm, Pitch 0.5mm, IPC Low Density)
3D model CY7C09369V-A100 (100-Pin Thin Quad Flat Pack 0.5 mm Pitch)
pins: 1 A9L (in), 2 A10L (in), 3 A11L (in), 4 A12L (in), 5 A13L (in), 6 NC, 7 NC, 8 ~{LB}L (in), 9 ~{UB}L (in), 10 ~{CE0}L (in), 11 CE1L (in), 12 ~{CNTRST}L (in), 13 R/~{W}L (in), 14 ~{OE}L (in), 15 VCC (power), 16 ~{FT}/PIPEL (in), 17 I/O17L (io), 18 I/O16L (io), 19 VSS (power), 20 I/O15L (io), 21 I/O14L (io), 22 I/O13L (io), 23 I/O12L (io), 24 I/O11L (io), 25 I/O10L (io), 26 I/O9L (io), 27 I/O8L (io), 28 VCC (power), 29 I/O7L (io), 30 I/O6L (io), 31 I/O5L (io), 32 I/O4L (io), 33 I/O3L (io), 34 I/O2L (io), 35 GND (power), 36 I/O1L (io), 37 I/O0L (io), 38 GND (power), 39 I/O0R (io), 40 I/O1R (io), 41 I/O2R (io), 42 I/O3R (io), 43 I/O4R (io), 44 I/O5R (io), 45 I/O6R (io), 46 VCC (power), 47 I/O7R (io), 48 I/O8R (io), 49 I/O9R (io), 50 I/O10R (io), 51 I/O11R (io), 52 I/O12R (io), 53 I/O13R (io), 54 I/O14R (io), 55 I/O15R (io), 56 I/O16R (io), 57 GND (power), 58 I/O17R (io), 59 ~{FT}/PIPER (in), 60 ~{OE}R (in), 61 GND (power), 62 R/~{W}R (in), 63 ~{CNTRST}R (in), 64 CE1R (in), 65 ~{CE}0R (in), 66 ~{UB}R (in), 67 ~{LB}R (in), 68 NC, 69 NC, 70 A13R (in), 71 A12R (in), 72 A11R (in), 73 A10R (in), 74 A9R (in), 75 A8R (in), 76 A7R (in), 77 A6R (in), 78 A5R (in), 79 A4R (in), 80 A3R (in), 81 A2R (in), 82 A1R (in), 83 A0R (in), 84 ~{CNTEN}R (in), 85 CLKR (in), 86 ~{ADS}R (in), 87 GND (power), 88 GND (power), 89 ~{ADS}L (in), 90 CLKL (in), 91 ~{CNTEN}L (in), 92 A0L (in), 93 A1L (in), 94 A2L (in), 95 A3L (in), 96 A4L (in), 97 A5L (in), 98 A6L (in), 99 A7L (in), 100 A8L (in)

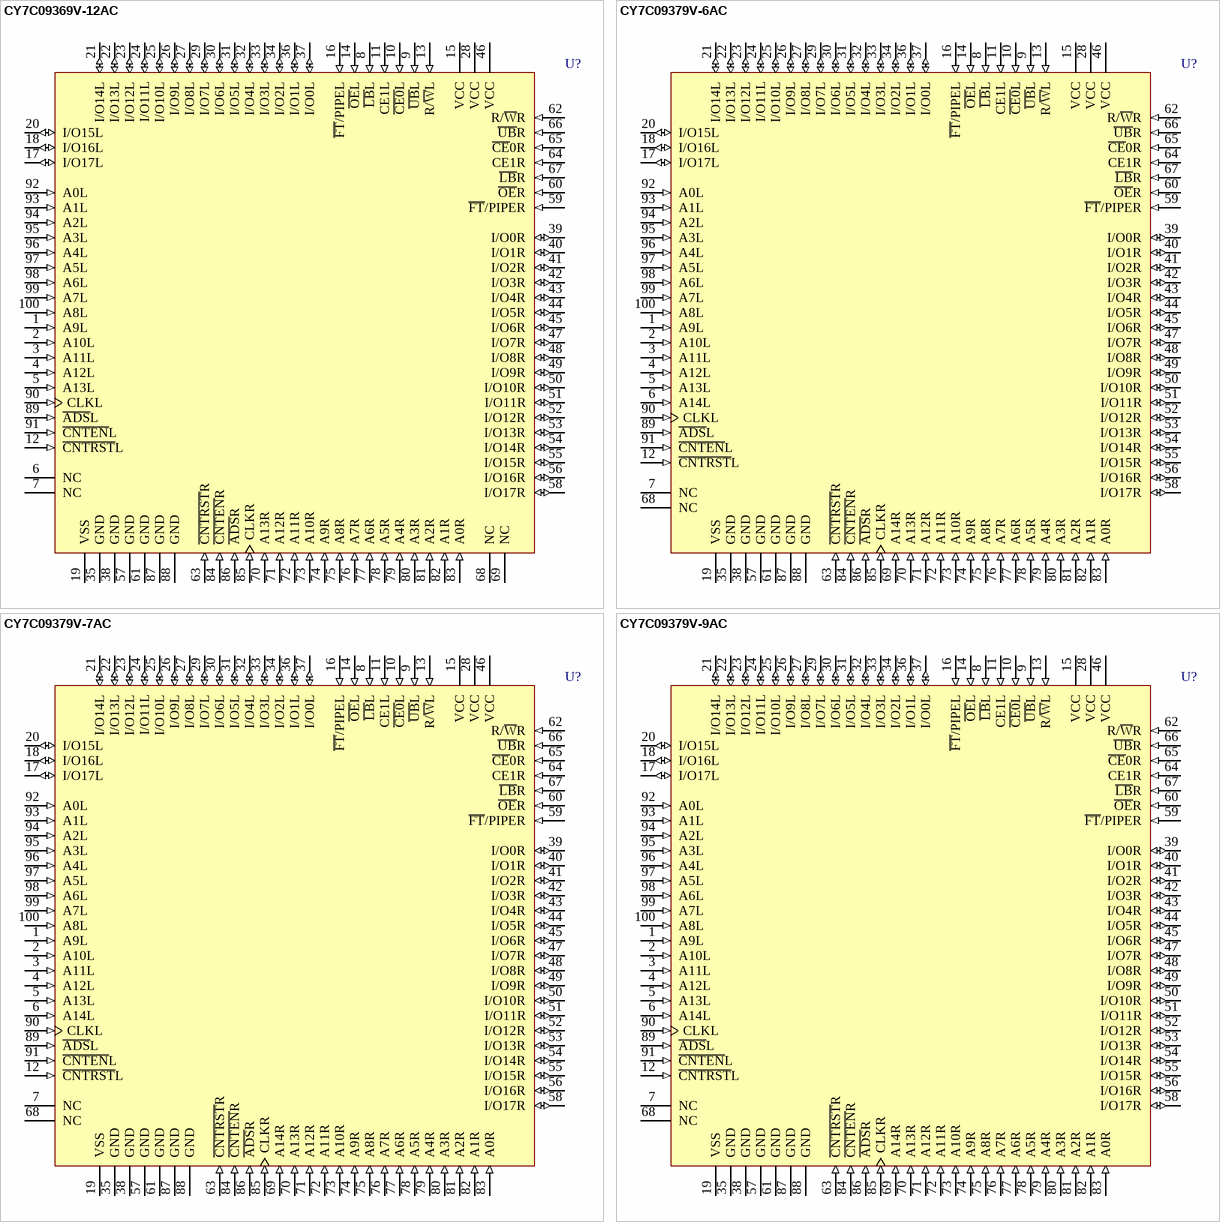
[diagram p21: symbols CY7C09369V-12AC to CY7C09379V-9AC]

## CY7C09369V-12AC
designator U?
3.3V 16K x 18 Synchronous Dual-Port Static RAM
footprint A100_N (Thin QFP, 100-Leads, Body 14x14mm, Pitch 0.5mm, IPC Medium Density)
footprint A100_L (Thin QFP, 100-Leads, Body 14x14mm, Pitch 0.5mm, IPC High Density)
footprint A100_M (Thin QFP, 100-Leads, Body 14x14mm, Pitch 0.5mm, IPC Low Density)
3D model CY7C09369V-A100 (100-Pin Thin Quad Flat Pack 0.5 mm Pitch)
pins: 1 A9L (in), 2 A10L (in), 3 A11L (in), 4 A12L (in), 5 A13L (in), 6 NC, 7 NC, 8 ~{LB}L (in), 9 ~{UB}L (in), 10 ~{CE0}L (in), 11 CE1L (in), 12 ~{CNTRST}L (in), 13 R/~{W}L (in), 14 ~{OE}L (in), 15 VCC (power), 16 ~{FT}/PIPEL (in), 17 I/O17L (io), 18 I/O16L (io), 19 VSS (power), 20 I/O15L (io), 21 I/O14L (io), 22 I/O13L (io), 23 I/O12L (io), 24 I/O11L (io), 25 I/O10L (io), 26 I/O9L (io), 27 I/O8L (io), 28 VCC (power), 29 I/O7L (io), 30 I/O6L (io), 31 I/O5L (io), 32 I/O4L (io), 33 I/O3L (io), 34 I/O2L (io), 35 GND (power), 36 I/O1L (io), 37 I/O0L (io), 38 GND (power), 39 I/O0R (io), 40 I/O1R (io), 41 I/O2R (io), 42 I/O3R (io), 43 I/O4R (io), 44 I/O5R (io), 45 I/O6R (io), 46 VCC (power), 47 I/O7R (io), 48 I/O8R (io), 49 I/O9R (io), 50 I/O10R (io), 51 I/O11R (io), 52 I/O12R (io), 53 I/O13R (io), 54 I/O14R (io), 55 I/O15R (io), 56 I/O16R (io), 57 GND (power), 58 I/O17R (io), 59 ~{FT}/PIPER (in), 60 ~{OE}R (in), 61 GND (power), 62 R/~{W}R (in), 63 ~{CNTRST}R (in), 64 CE1R (in), 65 ~{CE}0R (in), 66 ~{UB}R (in), 67 ~{LB}R (in), 68 NC, 69 NC, 70 A13R (in), 71 A12R (in), 72 A11R (in), 73 A10R (in), 74 A9R (in), 75 A8R (in), 76 A7R (in), 77 A6R (in), 78 A5R (in), 79 A4R (in), 80 A3R (in), 81 A2R (in), 82 A1R (in), 83 A0R (in), 84 ~{CNTEN}R (in), 85 CLKR (in), 86 ~{ADS}R (in), 87 GND (power), 88 GND (power), 89 ~{ADS}L (in), 90 CLKL (in), 91 ~{CNTEN}L (in), 92 A0L (in), 93 A1L (in), 94 A2L (in), 95 A3L (in), 96 A4L (in), 97 A5L (in), 98 A6L (in), 99 A7L (in), 100 A8L (in)

## CY7C09379V-6AC
designator U?
3.3V 32K x 18 Synchronous Dual-Port Static RAM
footprint A100_N (Thin QFP, 100-Leads, Body 14x14mm, Pitch 0.5mm, IPC Medium Density)
footprint A100_L (Thin QFP, 100-Leads, Body 14x14mm, Pitch 0.5mm, IPC High Density)
footprint A100_M (Thin QFP, 100-Leads, Body 14x14mm, Pitch 0.5mm, IPC Low Density)
3D model CY7C09379V-A100 (100-Pin Thin Quad Flat Pack 0.5 mm Pitch)
pins: 1 A9L (in), 2 A10L (in), 3 A11L (in), 4 A12L (in), 5 A13L (in), 6 A14L (in), 7 NC, 8 ~{LB}L (in), 9 ~{UB}L (in), 10 ~{CE0}L (in), 11 CE1L (in), 12 ~{CNTRST}L (in), 13 R/~{W}L (in), 14 ~{OE}L (in), 15 VCC (power), 16 ~{FT}/PIPEL (in), 17 I/O17L (io), 18 I/O16L (io), 19 VSS (power), 20 I/O15L (io), 21 I/O14L (io), 22 I/O13L (io), 23 I/O12L (io), 24 I/O11L (io), 25 I/O10L (io), 26 I/O9L (io), 27 I/O8L (io), 28 VCC (power), 29 I/O7L (io), 30 I/O6L (io), 31 I/O5L (io), 32 I/O4L (io), 33 I/O3L (io), 34 I/O2L (io), 35 GND (power), 36 I/O1L (io), 37 I/O0L (io), 38 GND (power), 39 I/O0R (io), 40 I/O1R (io), 41 I/O2R (io), 42 I/O3R (io), 43 I/O4R (io), 44 I/O5R (io), 45 I/O6R (io), 46 VCC (power), 47 I/O7R (io), 48 I/O8R (io), 49 I/O9R (io), 50 I/O10R (io), 51 I/O11R (io), 52 I/O12R (io), 53 I/O13R (io), 54 I/O14R (io), 55 I/O15R (io), 56 I/O16R (io), 57 GND (power), 58 I/O17R (io), 59 ~{FT}/PIPER (in), 60 ~{OE}R (in), 61 GND (power), 62 R/~{W}R (in), 63 ~{CNTRST}R (in), 64 CE1R (in), 65 ~{CE}0R (in), 66 ~{UB}R (in), 67 ~{LB}R (in), 68 NC, 69 A14R (in), 70 A13R (in), 71 A12R (in), 72 A11R (in), 73 A10R (in), 74 A9R (in), 75 A8R (in), 76 A7R (in), 77 A6R (in), 78 A5R (in), 79 A4R (in), 80 A3R (in), 81 A2R (in), 82 A1R (in), 83 A0R (in), 84 ~{CNTEN}R (in), 85 CLKR (in), 86 ~{ADS}R (in), 87 GND (power), 88 GND (power), 89 ~{ADS}L (in), 90 CLKL (in), 91 ~{CNTEN}L (in), 92 A0L (in), 93 A1L (in), 94 A2L (in), 95 A3L (in), 96 A4L (in), 97 A5L (in), 98 A6L (in), 99 A7L (in), 100 A8L (in)

## CY7C09379V-7AC
designator U?
3.3V 32K x 18 Synchronous Dual-Port Static RAM
footprint A100_N (Thin QFP, 100-Leads, Body 14x14mm, Pitch 0.5mm, IPC Medium Density)
footprint A100_L (Thin QFP, 100-Leads, Body 14x14mm, Pitch 0.5mm, IPC High Density)
footprint A100_M (Thin QFP, 100-Leads, Body 14x14mm, Pitch 0.5mm, IPC Low Density)
3D model CY7C09379V-A100 (100-Pin Thin Quad Flat Pack 0.5 mm Pitch)
pins: 1 A9L (in), 2 A10L (in), 3 A11L (in), 4 A12L (in), 5 A13L (in), 6 A14L (in), 7 NC, 8 ~{LB}L (in), 9 ~{UB}L (in), 10 ~{CE0}L (in), 11 CE1L (in), 12 ~{CNTRST}L (in), 13 R/~{W}L (in), 14 ~{OE}L (in), 15 VCC (power), 16 ~{FT}/PIPEL (in), 17 I/O17L (io), 18 I/O16L (io), 19 VSS (power), 20 I/O15L (io), 21 I/O14L (io), 22 I/O13L (io), 23 I/O12L (io), 24 I/O11L (io), 25 I/O10L (io), 26 I/O9L (io), 27 I/O8L (io), 28 VCC (power), 29 I/O7L (io), 30 I/O6L (io), 31 I/O5L (io), 32 I/O4L (io), 33 I/O3L (io), 34 I/O2L (io), 35 GND (power), 36 I/O1L (io), 37 I/O0L (io), 38 GND (power), 39 I/O0R (io), 40 I/O1R (io), 41 I/O2R (io), 42 I/O3R (io), 43 I/O4R (io), 44 I/O5R (io), 45 I/O6R (io), 46 VCC (power), 47 I/O7R (io), 48 I/O8R (io), 49 I/O9R (io), 50 I/O10R (io), 51 I/O11R (io), 52 I/O12R (io), 53 I/O13R (io), 54 I/O14R (io), 55 I/O15R (io), 56 I/O16R (io), 57 GND (power), 58 I/O17R (io), 59 ~{FT}/PIPER (in), 60 ~{OE}R (in), 61 GND (power), 62 R/~{W}R (in), 63 ~{CNTRST}R (in), 64 CE1R (in), 65 ~{CE}0R (in), 66 ~{UB}R (in), 67 ~{LB}R (in), 68 NC, 69 A14R (in), 70 A13R (in), 71 A12R (in), 72 A11R (in), 73 A10R (in), 74 A9R (in), 75 A8R (in), 76 A7R (in), 77 A6R (in), 78 A5R (in), 79 A4R (in), 80 A3R (in), 81 A2R (in), 82 A1R (in), 83 A0R (in), 84 ~{CNTEN}R (in), 85 CLKR (in), 86 ~{ADS}R (in), 87 GND (power), 88 GND (power), 89 ~{ADS}L (in), 90 CLKL (in), 91 ~{CNTEN}L (in), 92 A0L (in), 93 A1L (in), 94 A2L (in), 95 A3L (in), 96 A4L (in), 97 A5L (in), 98 A6L (in), 99 A7L (in), 100 A8L (in)

## CY7C09379V-9AC
designator U?
3.3V 32K x 18 Synchronous Dual-Port Static RAM
footprint A100_N (Thin QFP, 100-Leads, Body 14x14mm, Pitch 0.5mm, IPC Medium Density)
footprint A100_L (Thin QFP, 100-Leads, Body 14x14mm, Pitch 0.5mm, IPC High Density)
footprint A100_M (Thin QFP, 100-Leads, Body 14x14mm, Pitch 0.5mm, IPC Low Density)
3D model CY7C09379V-A100 (100-Pin Thin Quad Flat Pack 0.5 mm Pitch)
pins: 1 A9L (in), 2 A10L (in), 3 A11L (in), 4 A12L (in), 5 A13L (in), 6 A14L (in), 7 NC, 8 ~{LB}L (in), 9 ~{UB}L (in), 10 ~{CE0}L (in), 11 CE1L (in), 12 ~{CNTRST}L (in), 13 R/~{W}L (in), 14 ~{OE}L (in), 15 VCC (power), 16 ~{FT}/PIPEL (in), 17 I/O17L (io), 18 I/O16L (io), 19 VSS (power), 20 I/O15L (io), 21 I/O14L (io), 22 I/O13L (io), 23 I/O12L (io), 24 I/O11L (io), 25 I/O10L (io), 26 I/O9L (io), 27 I/O8L (io), 28 VCC (power), 29 I/O7L (io), 30 I/O6L (io), 31 I/O5L (io), 32 I/O4L (io), 33 I/O3L (io), 34 I/O2L (io), 35 GND (power), 36 I/O1L (io), 37 I/O0L (io), 38 GND (power), 39 I/O0R (io), 40 I/O1R (io), 41 I/O2R (io), 42 I/O3R (io), 43 I/O4R (io), 44 I/O5R (io), 45 I/O6R (io), 46 VCC (power), 47 I/O7R (io), 48 I/O8R (io), 49 I/O9R (io), 50 I/O10R (io), 51 I/O11R (io), 52 I/O12R (io), 53 I/O13R (io), 54 I/O14R (io), 55 I/O15R (io), 56 I/O16R (io), 57 GND (power), 58 I/O17R (io), 59 ~{FT}/PIPER (in), 60 ~{OE}R (in), 61 GND (power), 62 R/~{W}R (in), 63 ~{CNTRST}R (in), 64 CE1R (in), 65 ~{CE}0R (in), 66 ~{UB}R (in), 67 ~{LB}R (in), 68 NC, 69 A14R (in), 70 A13R (in), 71 A12R (in), 72 A11R (in), 73 A10R (in), 74 A9R (in), 75 A8R (in), 76 A7R (in), 77 A6R (in), 78 A5R (in), 79 A4R (in), 80 A3R (in), 81 A2R (in), 82 A1R (in), 83 A0R (in), 84 ~{CNTEN}R (in), 85 CLKR (in), 86 ~{ADS}R (in), 87 GND (power), 88 GND (power), 89 ~{ADS}L (in), 90 CLKL (in), 91 ~{CNTEN}L (in), 92 A0L (in), 93 A1L (in), 94 A2L (in), 95 A3L (in), 96 A4L (in), 97 A5L (in), 98 A6L (in), 99 A7L (in), 100 A8L (in)

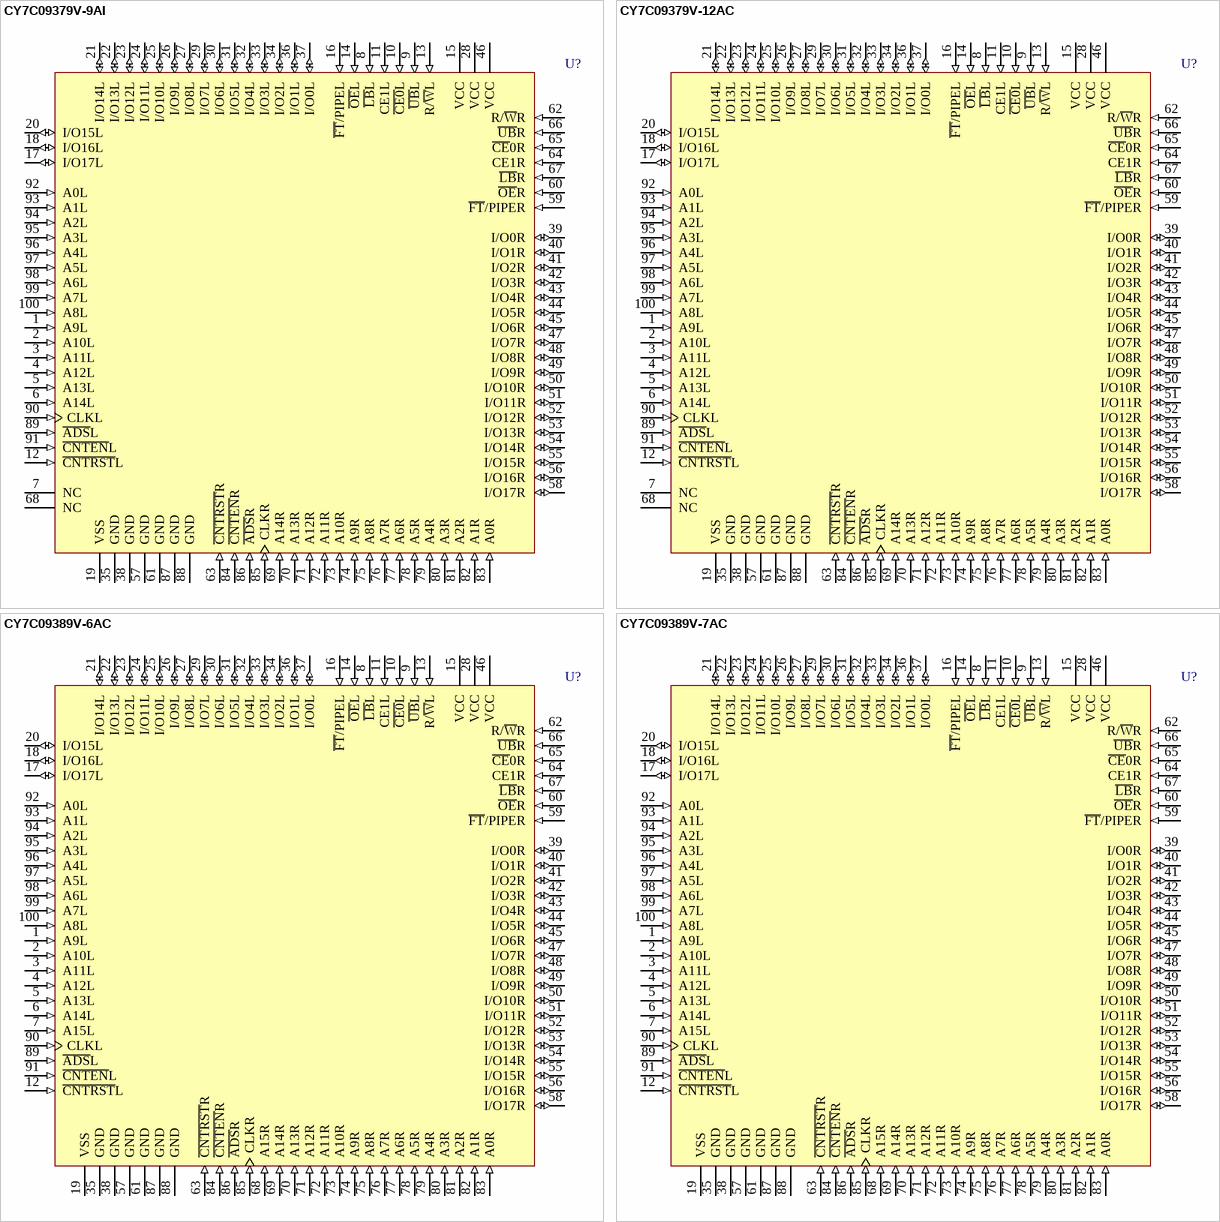
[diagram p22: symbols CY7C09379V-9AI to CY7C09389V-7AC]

## CY7C09379V-9AI
designator U?
3.3V 32K x 18 Synchronous Dual-Port Static RAM
footprint A100_N (Thin QFP, 100-Leads, Body 14x14mm, Pitch 0.5mm, IPC Medium Density)
footprint A100_L (Thin QFP, 100-Leads, Body 14x14mm, Pitch 0.5mm, IPC High Density)
footprint A100_M (Thin QFP, 100-Leads, Body 14x14mm, Pitch 0.5mm, IPC Low Density)
3D model CY7C09379V-A100 (100-Pin Thin Quad Flat Pack 0.5 mm Pitch)
pins: 1 A9L (in), 2 A10L (in), 3 A11L (in), 4 A12L (in), 5 A13L (in), 6 A14L (in), 7 NC, 8 ~{LB}L (in), 9 ~{UB}L (in), 10 ~{CE0}L (in), 11 CE1L (in), 12 ~{CNTRST}L (in), 13 R/~{W}L (in), 14 ~{OE}L (in), 15 VCC (power), 16 ~{FT}/PIPEL (in), 17 I/O17L (io), 18 I/O16L (io), 19 VSS (power), 20 I/O15L (io), 21 I/O14L (io), 22 I/O13L (io), 23 I/O12L (io), 24 I/O11L (io), 25 I/O10L (io), 26 I/O9L (io), 27 I/O8L (io), 28 VCC (power), 29 I/O7L (io), 30 I/O6L (io), 31 I/O5L (io), 32 I/O4L (io), 33 I/O3L (io), 34 I/O2L (io), 35 GND (power), 36 I/O1L (io), 37 I/O0L (io), 38 GND (power), 39 I/O0R (io), 40 I/O1R (io), 41 I/O2R (io), 42 I/O3R (io), 43 I/O4R (io), 44 I/O5R (io), 45 I/O6R (io), 46 VCC (power), 47 I/O7R (io), 48 I/O8R (io), 49 I/O9R (io), 50 I/O10R (io), 51 I/O11R (io), 52 I/O12R (io), 53 I/O13R (io), 54 I/O14R (io), 55 I/O15R (io), 56 I/O16R (io), 57 GND (power), 58 I/O17R (io), 59 ~{FT}/PIPER (in), 60 ~{OE}R (in), 61 GND (power), 62 R/~{W}R (in), 63 ~{CNTRST}R (in), 64 CE1R (in), 65 ~{CE}0R (in), 66 ~{UB}R (in), 67 ~{LB}R (in), 68 NC, 69 A14R (in), 70 A13R (in), 71 A12R (in), 72 A11R (in), 73 A10R (in), 74 A9R (in), 75 A8R (in), 76 A7R (in), 77 A6R (in), 78 A5R (in), 79 A4R (in), 80 A3R (in), 81 A2R (in), 82 A1R (in), 83 A0R (in), 84 ~{CNTEN}R (in), 85 CLKR (in), 86 ~{ADS}R (in), 87 GND (power), 88 GND (power), 89 ~{ADS}L (in), 90 CLKL (in), 91 ~{CNTEN}L (in), 92 A0L (in), 93 A1L (in), 94 A2L (in), 95 A3L (in), 96 A4L (in), 97 A5L (in), 98 A6L (in), 99 A7L (in), 100 A8L (in)

## CY7C09379V-12AC
designator U?
3.3V 32K x 18 Synchronous Dual-Port Static RAM
footprint A100_N (Thin QFP, 100-Leads, Body 14x14mm, Pitch 0.5mm, IPC Medium Density)
footprint A100_L (Thin QFP, 100-Leads, Body 14x14mm, Pitch 0.5mm, IPC High Density)
footprint A100_M (Thin QFP, 100-Leads, Body 14x14mm, Pitch 0.5mm, IPC Low Density)
3D model CY7C09379V-A100 (100-Pin Thin Quad Flat Pack 0.5 mm Pitch)
pins: 1 A9L (in), 2 A10L (in), 3 A11L (in), 4 A12L (in), 5 A13L (in), 6 A14L (in), 7 NC, 8 ~{LB}L (in), 9 ~{UB}L (in), 10 ~{CE0}L (in), 11 CE1L (in), 12 ~{CNTRST}L (in), 13 R/~{W}L (in), 14 ~{OE}L (in), 15 VCC (power), 16 ~{FT}/PIPEL (in), 17 I/O17L (io), 18 I/O16L (io), 19 VSS (power), 20 I/O15L (io), 21 I/O14L (io), 22 I/O13L (io), 23 I/O12L (io), 24 I/O11L (io), 25 I/O10L (io), 26 I/O9L (io), 27 I/O8L (io), 28 VCC (power), 29 I/O7L (io), 30 I/O6L (io), 31 I/O5L (io), 32 I/O4L (io), 33 I/O3L (io), 34 I/O2L (io), 35 GND (power), 36 I/O1L (io), 37 I/O0L (io), 38 GND (power), 39 I/O0R (io), 40 I/O1R (io), 41 I/O2R (io), 42 I/O3R (io), 43 I/O4R (io), 44 I/O5R (io), 45 I/O6R (io), 46 VCC (power), 47 I/O7R (io), 48 I/O8R (io), 49 I/O9R (io), 50 I/O10R (io), 51 I/O11R (io), 52 I/O12R (io), 53 I/O13R (io), 54 I/O14R (io), 55 I/O15R (io), 56 I/O16R (io), 57 GND (power), 58 I/O17R (io), 59 ~{FT}/PIPER (in), 60 ~{OE}R (in), 61 GND (power), 62 R/~{W}R (in), 63 ~{CNTRST}R (in), 64 CE1R (in), 65 ~{CE}0R (in), 66 ~{UB}R (in), 67 ~{LB}R (in), 68 NC, 69 A14R (in), 70 A13R (in), 71 A12R (in), 72 A11R (in), 73 A10R (in), 74 A9R (in), 75 A8R (in), 76 A7R (in), 77 A6R (in), 78 A5R (in), 79 A4R (in), 80 A3R (in), 81 A2R (in), 82 A1R (in), 83 A0R (in), 84 ~{CNTEN}R (in), 85 CLKR (in), 86 ~{ADS}R (in), 87 GND (power), 88 GND (power), 89 ~{ADS}L (in), 90 CLKL (in), 91 ~{CNTEN}L (in), 92 A0L (in), 93 A1L (in), 94 A2L (in), 95 A3L (in), 96 A4L (in), 97 A5L (in), 98 A6L (in), 99 A7L (in), 100 A8L (in)

## CY7C09389V-6AC
designator U?
3.3V 64K x 18 Synchronous Dual-Port Static RAM
footprint A100_N (Thin QFP, 100-Leads, Body 14x14mm, Pitch 0.5mm, IPC Medium Density)
footprint A100_L (Thin QFP, 100-Leads, Body 14x14mm, Pitch 0.5mm, IPC High Density)
footprint A100_M (Thin QFP, 100-Leads, Body 14x14mm, Pitch 0.5mm, IPC Low Density)
3D model CY7C09389V-A100 (100-Pin Thin Quad Flat Pack 0.5 mm Pitch)
pins: 1 A9L (in), 2 A10L (in), 3 A11L (in), 4 A12L (in), 5 A13L (in), 6 A14L (in), 7 A15L (in), 8 ~{LB}L (in), 9 ~{UB}L (in), 10 ~{CE0}L (in), 11 CE1L (in), 12 ~{CNTRST}L (in), 13 R/~{W}L (in), 14 ~{OE}L (in), 15 VCC (power), 16 ~{FT}/PIPEL (in), 17 I/O17L (io), 18 I/O16L (io), 19 VSS (power), 20 I/O15L (io), 21 I/O14L (io), 22 I/O13L (io), 23 I/O12L (io), 24 I/O11L (io), 25 I/O10L (io), 26 I/O9L (io), 27 I/O8L (io), 28 VCC (power), 29 I/O7L (io), 30 I/O6L (io), 31 I/O5L (io), 32 I/O4L (io), 33 I/O3L (io), 34 I/O2L (io), 35 GND (power), 36 I/O1L (io), 37 I/O0L (io), 38 GND (power), 39 I/O0R (io), 40 I/O1R (io), 41 I/O2R (io), 42 I/O3R (io), 43 I/O4R (io), 44 I/O5R (io), 45 I/O6R (io), 46 VCC (power), 47 I/O7R (io), 48 I/O8R (io), 49 I/O9R (io), 50 I/O10R (io), 51 I/O11R (io), 52 I/O12R (io), 53 I/O13R (io), 54 I/O14R (io), 55 I/O15R (io), 56 I/O16R (io), 57 GND (power), 58 I/O17R (io), 59 ~{FT}/PIPER (in), 60 ~{OE}R (in), 61 GND (power), 62 R/~{W}R (in), 63 ~{CNTRST}R (in), 64 CE1R (in), 65 ~{CE}0R (in), 66 ~{UB}R (in), 67 ~{LB}R (in), 68 A15R (in), 69 A14R (in), 70 A13R (in), 71 A12R (in), 72 A11R (in), 73 A10R (in), 74 A9R (in), 75 A8R (in), 76 A7R (in), 77 A6R (in), 78 A5R (in), 79 A4R (in), 80 A3R (in), 81 A2R (in), 82 A1R (in), 83 A0R (in), 84 ~{CNTEN}R (in), 85 CLKR (in), 86 ~{ADS}R (in), 87 GND (power), 88 GND (power), 89 ~{ADS}L (in), 90 CLKL (in), 91 ~{CNTEN}L (in), 92 A0L (in), 93 A1L (in), 94 A2L (in), 95 A3L (in), 96 A4L (in), 97 A5L (in), 98 A6L (in), 99 A7L (in), 100 A8L (in)

## CY7C09389V-7AC
designator U?
3.3V 64K x 18 Synchronous Dual-Port Static RAM
footprint A100_N (Thin QFP, 100-Leads, Body 14x14mm, Pitch 0.5mm, IPC Medium Density)
footprint A100_L (Thin QFP, 100-Leads, Body 14x14mm, Pitch 0.5mm, IPC High Density)
footprint A100_M (Thin QFP, 100-Leads, Body 14x14mm, Pitch 0.5mm, IPC Low Density)
3D model CY7C09389V-A100 (100-Pin Thin Quad Flat Pack 0.5 mm Pitch)
pins: 1 A9L (in), 2 A10L (in), 3 A11L (in), 4 A12L (in), 5 A13L (in), 6 A14L (in), 7 A15L (in), 8 ~{LB}L (in), 9 ~{UB}L (in), 10 ~{CE0}L (in), 11 CE1L (in), 12 ~{CNTRST}L (in), 13 R/~{W}L (in), 14 ~{OE}L (in), 15 VCC (power), 16 ~{FT}/PIPEL (in), 17 I/O17L (io), 18 I/O16L (io), 19 VSS (power), 20 I/O15L (io), 21 I/O14L (io), 22 I/O13L (io), 23 I/O12L (io), 24 I/O11L (io), 25 I/O10L (io), 26 I/O9L (io), 27 I/O8L (io), 28 VCC (power), 29 I/O7L (io), 30 I/O6L (io), 31 I/O5L (io), 32 I/O4L (io), 33 I/O3L (io), 34 I/O2L (io), 35 GND (power), 36 I/O1L (io), 37 I/O0L (io), 38 GND (power), 39 I/O0R (io), 40 I/O1R (io), 41 I/O2R (io), 42 I/O3R (io), 43 I/O4R (io), 44 I/O5R (io), 45 I/O6R (io), 46 VCC (power), 47 I/O7R (io), 48 I/O8R (io), 49 I/O9R (io), 50 I/O10R (io), 51 I/O11R (io), 52 I/O12R (io), 53 I/O13R (io), 54 I/O14R (io), 55 I/O15R (io), 56 I/O16R (io), 57 GND (power), 58 I/O17R (io), 59 ~{FT}/PIPER (in), 60 ~{OE}R (in), 61 GND (power), 62 R/~{W}R (in), 63 ~{CNTRST}R (in), 64 CE1R (in), 65 ~{CE}0R (in), 66 ~{UB}R (in), 67 ~{LB}R (in), 68 A15R (in), 69 A14R (in), 70 A13R (in), 71 A12R (in), 72 A11R (in), 73 A10R (in), 74 A9R (in), 75 A8R (in), 76 A7R (in), 77 A6R (in), 78 A5R (in), 79 A4R (in), 80 A3R (in), 81 A2R (in), 82 A1R (in), 83 A0R (in), 84 ~{CNTEN}R (in), 85 CLKR (in), 86 ~{ADS}R (in), 87 GND (power), 88 GND (power), 89 ~{ADS}L (in), 90 CLKL (in), 91 ~{CNTEN}L (in), 92 A0L (in), 93 A1L (in), 94 A2L (in), 95 A3L (in), 96 A4L (in), 97 A5L (in), 98 A6L (in), 99 A7L (in), 100 A8L (in)

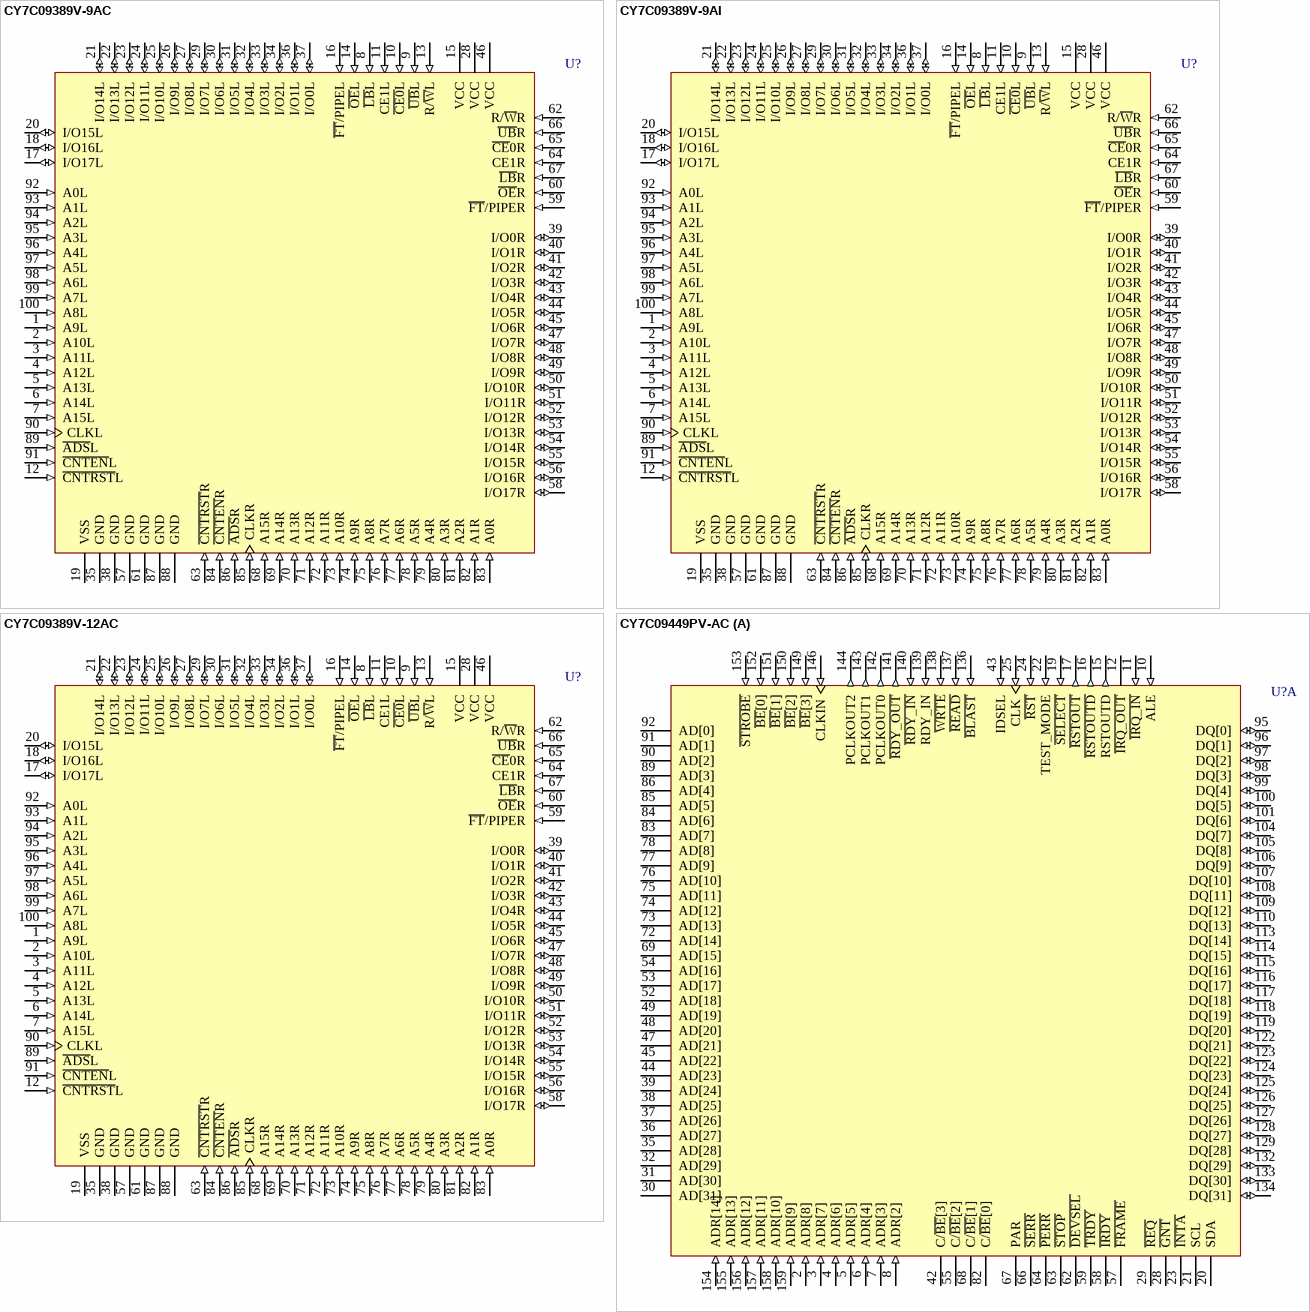
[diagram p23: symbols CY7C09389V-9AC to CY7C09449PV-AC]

## CY7C09389V-9AC
designator U?
3.3V 64K x 18 Synchronous Dual-Port Static RAM
footprint A100_N (Thin QFP, 100-Leads, Body 14x14mm, Pitch 0.5mm, IPC Medium Density)
footprint A100_L (Thin QFP, 100-Leads, Body 14x14mm, Pitch 0.5mm, IPC High Density)
footprint A100_M (Thin QFP, 100-Leads, Body 14x14mm, Pitch 0.5mm, IPC Low Density)
3D model CY7C09389V-A100 (100-Pin Thin Quad Flat Pack 0.5 mm Pitch)
pins: 1 A9L (in), 2 A10L (in), 3 A11L (in), 4 A12L (in), 5 A13L (in), 6 A14L (in), 7 A15L (in), 8 ~{LB}L (in), 9 ~{UB}L (in), 10 ~{CE0}L (in), 11 CE1L (in), 12 ~{CNTRST}L (in), 13 R/~{W}L (in), 14 ~{OE}L (in), 15 VCC (power), 16 ~{FT}/PIPEL (in), 17 I/O17L (io), 18 I/O16L (io), 19 VSS (power), 20 I/O15L (io), 21 I/O14L (io), 22 I/O13L (io), 23 I/O12L (io), 24 I/O11L (io), 25 I/O10L (io), 26 I/O9L (io), 27 I/O8L (io), 28 VCC (power), 29 I/O7L (io), 30 I/O6L (io), 31 I/O5L (io), 32 I/O4L (io), 33 I/O3L (io), 34 I/O2L (io), 35 GND (power), 36 I/O1L (io), 37 I/O0L (io), 38 GND (power), 39 I/O0R (io), 40 I/O1R (io), 41 I/O2R (io), 42 I/O3R (io), 43 I/O4R (io), 44 I/O5R (io), 45 I/O6R (io), 46 VCC (power), 47 I/O7R (io), 48 I/O8R (io), 49 I/O9R (io), 50 I/O10R (io), 51 I/O11R (io), 52 I/O12R (io), 53 I/O13R (io), 54 I/O14R (io), 55 I/O15R (io), 56 I/O16R (io), 57 GND (power), 58 I/O17R (io), 59 ~{FT}/PIPER (in), 60 ~{OE}R (in), 61 GND (power), 62 R/~{W}R (in), 63 ~{CNTRST}R (in), 64 CE1R (in), 65 ~{CE}0R (in), 66 ~{UB}R (in), 67 ~{LB}R (in), 68 A15R (in), 69 A14R (in), 70 A13R (in), 71 A12R (in), 72 A11R (in), 73 A10R (in), 74 A9R (in), 75 A8R (in), 76 A7R (in), 77 A6R (in), 78 A5R (in), 79 A4R (in), 80 A3R (in), 81 A2R (in), 82 A1R (in), 83 A0R (in), 84 ~{CNTEN}R (in), 85 CLKR (in), 86 ~{ADS}R (in), 87 GND (power), 88 GND (power), 89 ~{ADS}L (in), 90 CLKL (in), 91 ~{CNTEN}L (in), 92 A0L (in), 93 A1L (in), 94 A2L (in), 95 A3L (in), 96 A4L (in), 97 A5L (in), 98 A6L (in), 99 A7L (in), 100 A8L (in)

## CY7C09389V-9AI
designator U?
3.3V 64K x 18 Synchronous Dual-Port Static RAM
footprint A100_N (Thin QFP, 100-Leads, Body 14x14mm, Pitch 0.5mm, IPC Medium Density)
footprint A100_L (Thin QFP, 100-Leads, Body 14x14mm, Pitch 0.5mm, IPC High Density)
footprint A100_M (Thin QFP, 100-Leads, Body 14x14mm, Pitch 0.5mm, IPC Low Density)
3D model CY7C09389V-A100 (100-Pin Thin Quad Flat Pack 0.5 mm Pitch)
pins: 1 A9L (in), 2 A10L (in), 3 A11L (in), 4 A12L (in), 5 A13L (in), 6 A14L (in), 7 A15L (in), 8 ~{LB}L (in), 9 ~{UB}L (in), 10 ~{CE0}L (in), 11 CE1L (in), 12 ~{CNTRST}L (in), 13 R/~{W}L (in), 14 ~{OE}L (in), 15 VCC (power), 16 ~{FT}/PIPEL (in), 17 I/O17L (io), 18 I/O16L (io), 19 VSS (power), 20 I/O15L (io), 21 I/O14L (io), 22 I/O13L (io), 23 I/O12L (io), 24 I/O11L (io), 25 I/O10L (io), 26 I/O9L (io), 27 I/O8L (io), 28 VCC (power), 29 I/O7L (io), 30 I/O6L (io), 31 I/O5L (io), 32 I/O4L (io), 33 I/O3L (io), 34 I/O2L (io), 35 GND (power), 36 I/O1L (io), 37 I/O0L (io), 38 GND (power), 39 I/O0R (io), 40 I/O1R (io), 41 I/O2R (io), 42 I/O3R (io), 43 I/O4R (io), 44 I/O5R (io), 45 I/O6R (io), 46 VCC (power), 47 I/O7R (io), 48 I/O8R (io), 49 I/O9R (io), 50 I/O10R (io), 51 I/O11R (io), 52 I/O12R (io), 53 I/O13R (io), 54 I/O14R (io), 55 I/O15R (io), 56 I/O16R (io), 57 GND (power), 58 I/O17R (io), 59 ~{FT}/PIPER (in), 60 ~{OE}R (in), 61 GND (power), 62 R/~{W}R (in), 63 ~{CNTRST}R (in), 64 CE1R (in), 65 ~{CE}0R (in), 66 ~{UB}R (in), 67 ~{LB}R (in), 68 A15R (in), 69 A14R (in), 70 A13R (in), 71 A12R (in), 72 A11R (in), 73 A10R (in), 74 A9R (in), 75 A8R (in), 76 A7R (in), 77 A6R (in), 78 A5R (in), 79 A4R (in), 80 A3R (in), 81 A2R (in), 82 A1R (in), 83 A0R (in), 84 ~{CNTEN}R (in), 85 CLKR (in), 86 ~{ADS}R (in), 87 GND (power), 88 GND (power), 89 ~{ADS}L (in), 90 CLKL (in), 91 ~{CNTEN}L (in), 92 A0L (in), 93 A1L (in), 94 A2L (in), 95 A3L (in), 96 A4L (in), 97 A5L (in), 98 A6L (in), 99 A7L (in), 100 A8L (in)

## CY7C09389V-12AC
designator U?
3.3V 64K x 18 Synchronous Dual-Port Static RAM
footprint A100_N (Thin QFP, 100-Leads, Body 14x14mm, Pitch 0.5mm, IPC Medium Density)
footprint A100_L (Thin QFP, 100-Leads, Body 14x14mm, Pitch 0.5mm, IPC High Density)
footprint A100_M (Thin QFP, 100-Leads, Body 14x14mm, Pitch 0.5mm, IPC Low Density)
3D model CY7C09389V-A100 (100-Pin Thin Quad Flat Pack 0.5 mm Pitch)
pins: 1 A9L (in), 2 A10L (in), 3 A11L (in), 4 A12L (in), 5 A13L (in), 6 A14L (in), 7 A15L (in), 8 ~{LB}L (in), 9 ~{UB}L (in), 10 ~{CE0}L (in), 11 CE1L (in), 12 ~{CNTRST}L (in), 13 R/~{W}L (in), 14 ~{OE}L (in), 15 VCC (power), 16 ~{FT}/PIPEL (in), 17 I/O17L (io), 18 I/O16L (io), 19 VSS (power), 20 I/O15L (io), 21 I/O14L (io), 22 I/O13L (io), 23 I/O12L (io), 24 I/O11L (io), 25 I/O10L (io), 26 I/O9L (io), 27 I/O8L (io), 28 VCC (power), 29 I/O7L (io), 30 I/O6L (io), 31 I/O5L (io), 32 I/O4L (io), 33 I/O3L (io), 34 I/O2L (io), 35 GND (power), 36 I/O1L (io), 37 I/O0L (io), 38 GND (power), 39 I/O0R (io), 40 I/O1R (io), 41 I/O2R (io), 42 I/O3R (io), 43 I/O4R (io), 44 I/O5R (io), 45 I/O6R (io), 46 VCC (power), 47 I/O7R (io), 48 I/O8R (io), 49 I/O9R (io), 50 I/O10R (io), 51 I/O11R (io), 52 I/O12R (io), 53 I/O13R (io), 54 I/O14R (io), 55 I/O15R (io), 56 I/O16R (io), 57 GND (power), 58 I/O17R (io), 59 ~{FT}/PIPER (in), 60 ~{OE}R (in), 61 GND (power), 62 R/~{W}R (in), 63 ~{CNTRST}R (in), 64 CE1R (in), 65 ~{CE}0R (in), 66 ~{UB}R (in), 67 ~{LB}R (in), 68 A15R (in), 69 A14R (in), 70 A13R (in), 71 A12R (in), 72 A11R (in), 73 A10R (in), 74 A9R (in), 75 A8R (in), 76 A7R (in), 77 A6R (in), 78 A5R (in), 79 A4R (in), 80 A3R (in), 81 A2R (in), 82 A1R (in), 83 A0R (in), 84 ~{CNTEN}R (in), 85 CLKR (in), 86 ~{ADS}R (in), 87 GND (power), 88 GND (power), 89 ~{ADS}L (in), 90 CLKL (in), 91 ~{CNTEN}L (in), 92 A0L (in), 93 A1L (in), 94 A2L (in), 95 A3L (in), 96 A4L (in), 97 A5L (in), 98 A6L (in), 99 A7L (in), 100 A8L (in)

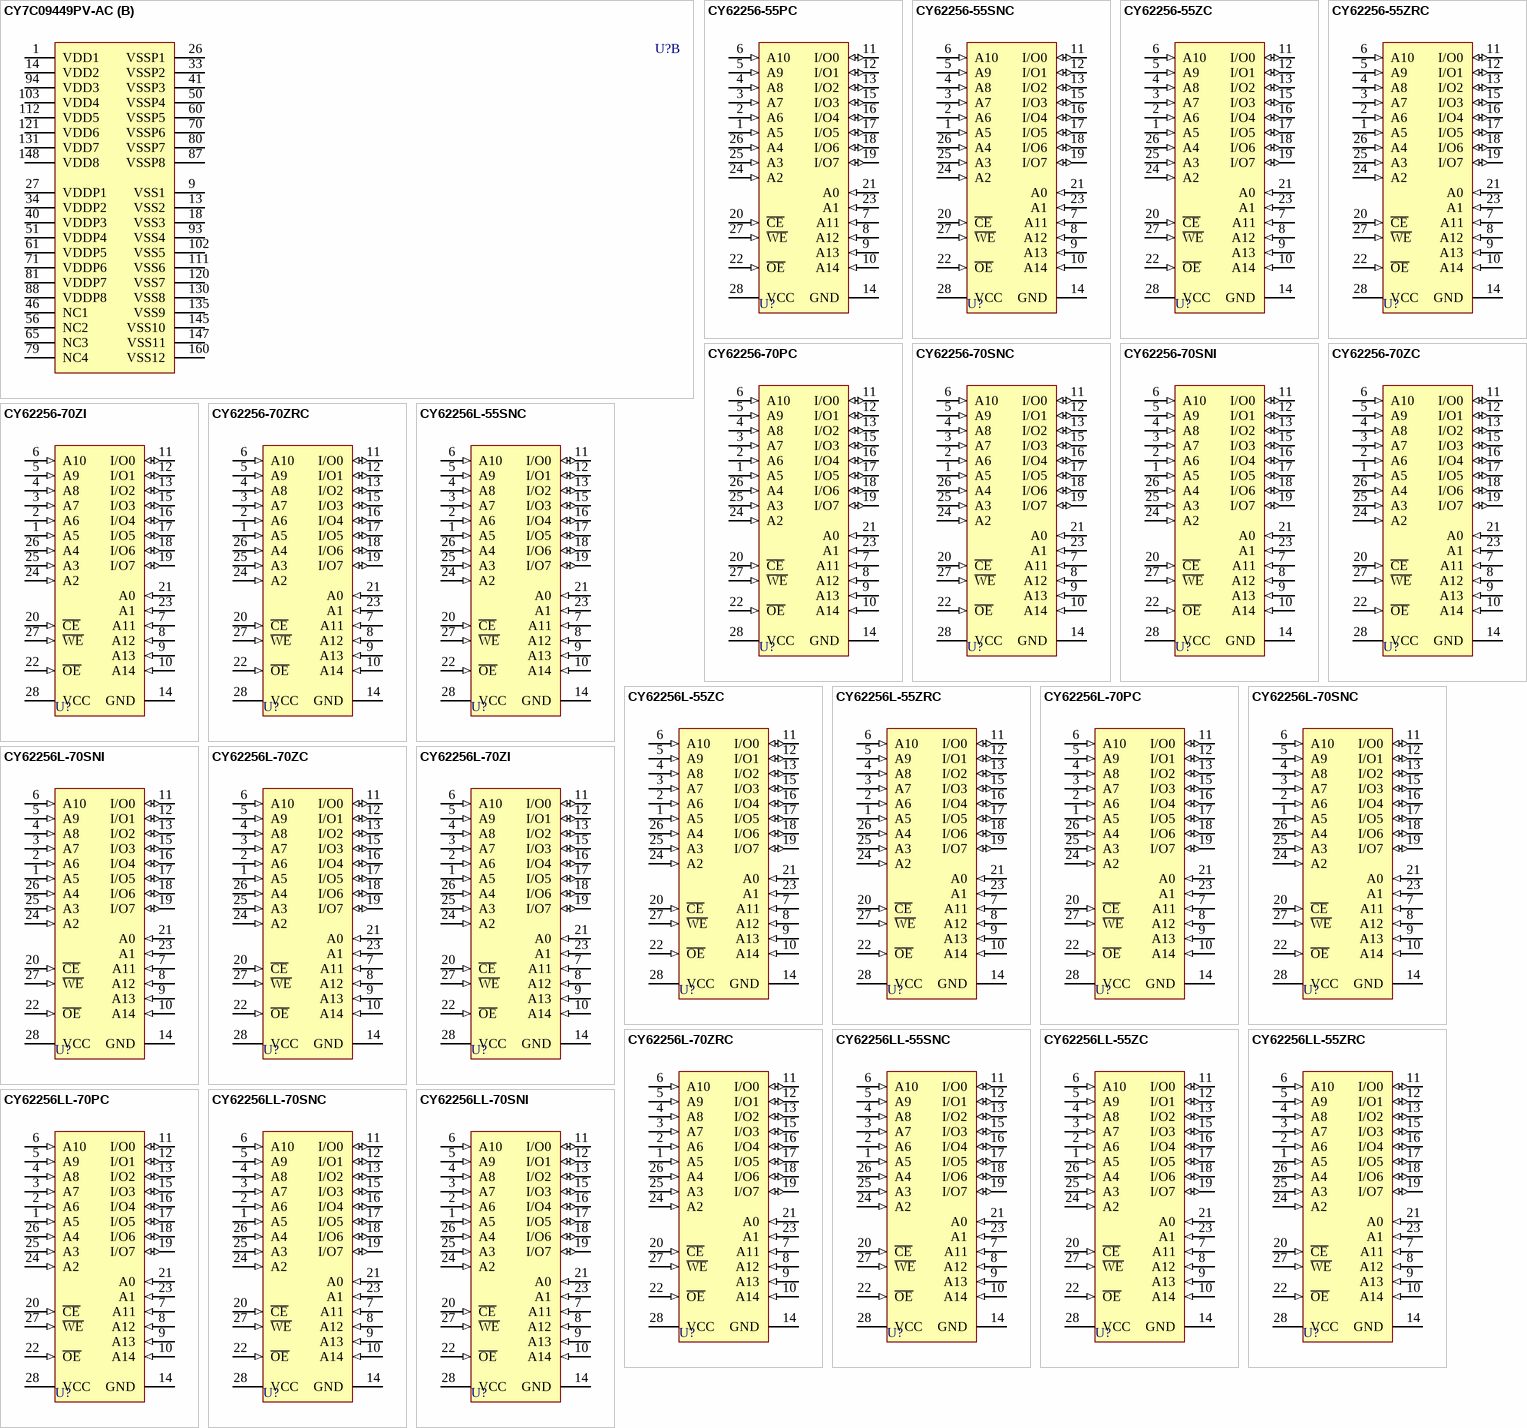
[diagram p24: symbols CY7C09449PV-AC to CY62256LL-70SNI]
